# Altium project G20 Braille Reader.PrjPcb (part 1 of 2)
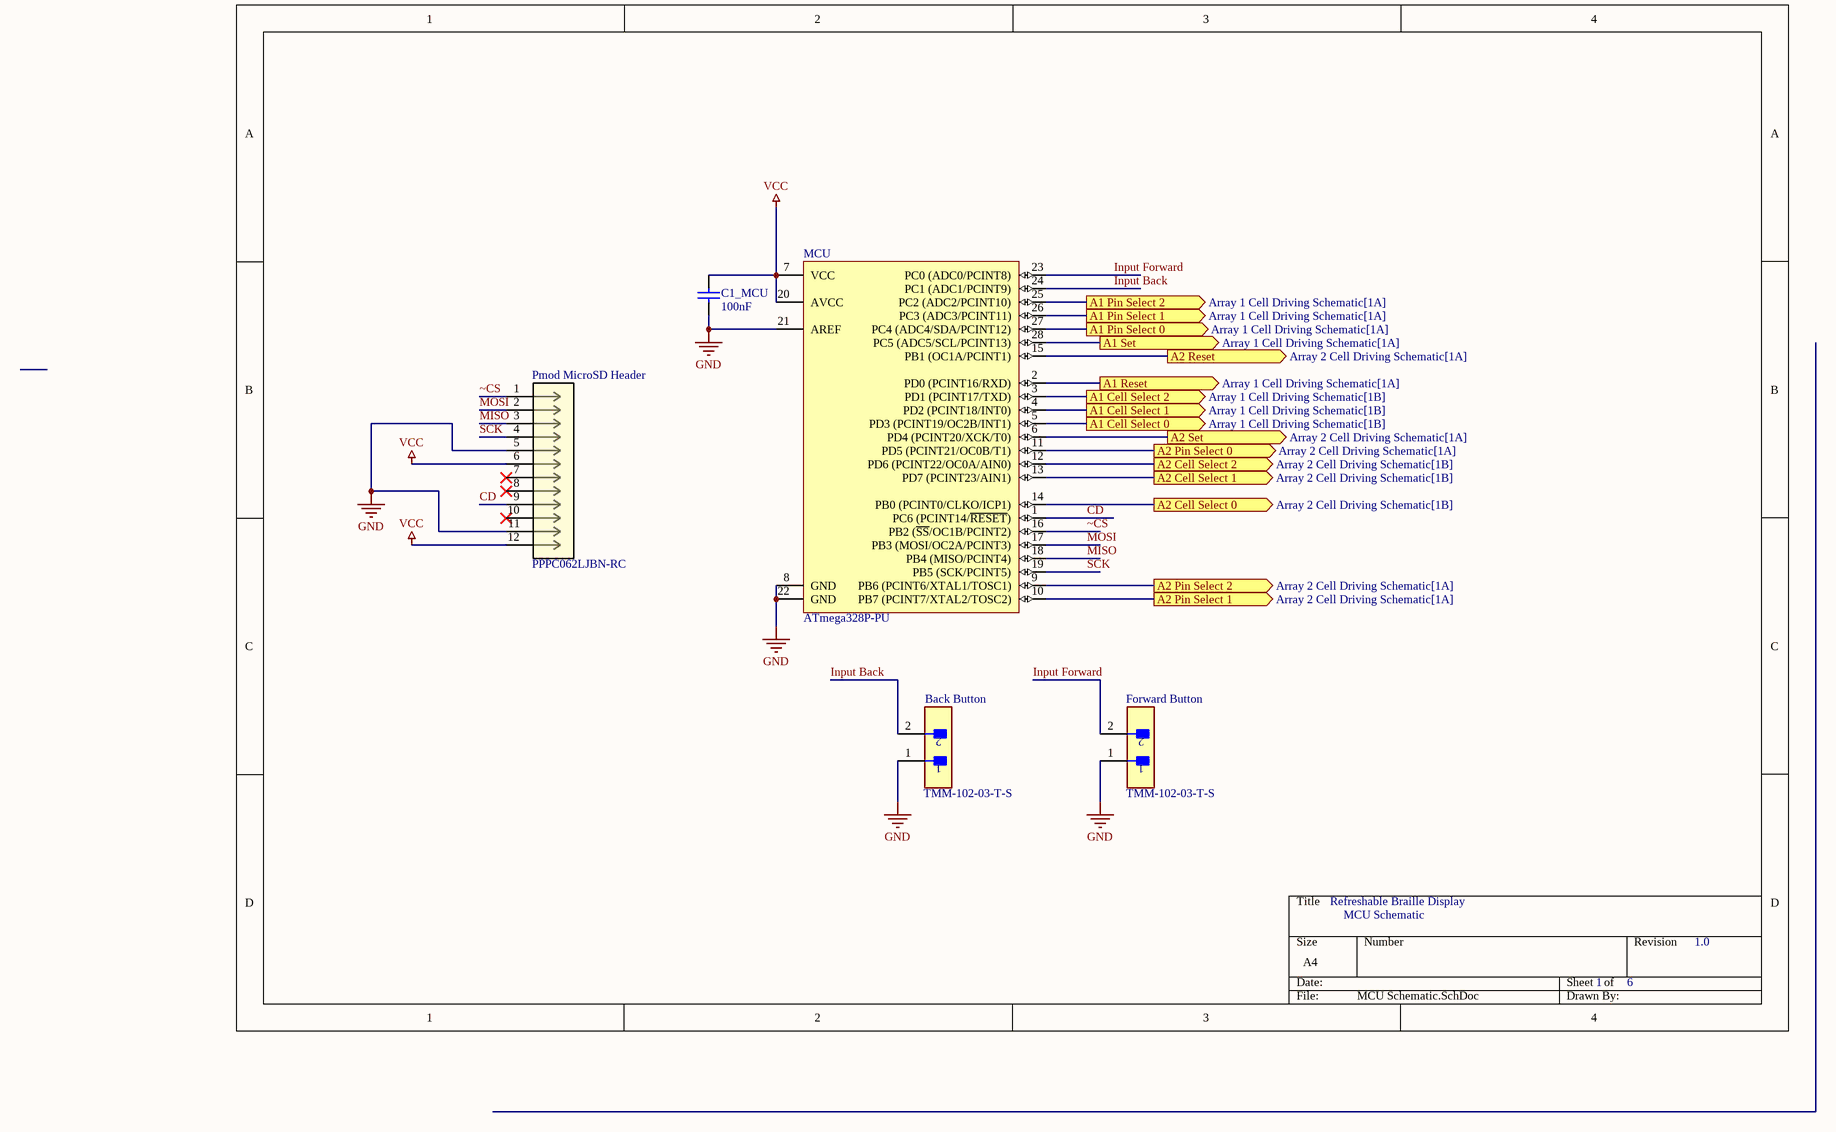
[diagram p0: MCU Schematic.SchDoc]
6 sheets, 206 parts. Net scope: flat (ports and power ports of the same name join across sheets).
Board files: G20 Braille Reader PCB.PcbDoc, Braille Cell.PcbDoc, G20 PCB Print.PcbDoc
Sheets:
  MCU Schematic.SchDoc
  Array 1 Cell Driving Schematic.SchDoc
  Array 1 Braille Cell Schematic.SchDoc
  Array 2 Cell Driving Schematic.SchDoc
  Array 2 Braille Cell Schematic.SchDoc
  Power and Voltage Regulation Schematic.SchDoc

## Sheet MCU Schematic.SchDoc
size A4; SheetNumber: 1; SheetTotal: 6

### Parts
Back_Button  TMM-102-03-T-S  [FP-TMM-102-03-T-S-MFG]
C1_MCU  100nF  [CAPC0805(2012)100_M]
Forward_Button  TMM-102-03-T-S  [FP-TMM-102-03-T-S-MFG]
MCU  ATmega328P-PU  [28P3]
Pmod_MicroSD_Header  PPPC062LJBN-RC  [CONN_PPPC062LJBN-RC_SUL]

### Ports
A1 Cell Select 0 (out, see Array 1 Cell Driving Schematic[1B]), A1 Cell Select 1 (out, see Array 1 Cell Driving Schematic[1B]), A1 Cell Select 2 (out, see Array 1 Cell Driving Schematic[1B]), A1 Pin Select 0 (out, see Array 1 Cell Driving Schematic[1A]), A1 Pin Select 1 (out, see Array 1 Cell Driving Schematic[1A]), A1 Pin Select 2 (out, see Array 1 Cell Driving Schematic[1A]), A1 Reset (out, see Array 1 Cell Driving Schematic[1A]), A1 Set (out, see Array 1 Cell Driving Schematic[1A]), A2 Cell Select 0 (out, see Array 2 Cell Driving Schematic[1B]), A2 Cell Select 1 (out, see Array 2 Cell Driving Schematic[1B]), A2 Cell Select 2 (out, see Array 2 Cell Driving Schematic[1B]), A2 Pin Select 0 (out, see Array 2 Cell Driving Schematic[1A]), A2 Pin Select 1 (out, see Array 2 Cell Driving Schematic[1A]), A2 Pin Select 2 (out, see Array 2 Cell Driving Schematic[1A]), A2 Reset (out, see Array 2 Cell Driving Schematic[1A]), A2 Set (out, see Array 2 Cell Driving Schematic[1A])

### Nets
GND: Back_Button.1 C1_MCU.1 Forward_Button.1 MCU.8(GND) MCU.21(AREF) MCU.22(GND) Pmod_MicroSD_Header.5 Pmod_MicroSD_Header.11
VCC: C1_MCU.2 MCU.7(VCC) MCU.20(AVCC) Pmod_MicroSD_Header.6 Pmod_MicroSD_Header.12
A2 Cell Select 0: MCU.14(PB0_(PCINT0/CLKO/ICP1)) ; port A2 Cell Select 0
A2 Cell Select 1: MCU.13(PD7_(PCINT23/AIN1)) ; port A2 Cell Select 1
A2 Cell Select 2: MCU.12(PD6_(PCINT22/OC0A/AIN0)) ; port A2 Cell Select 2
A2 Pin Select 0: MCU.11(PD5_(PCINT21/OC0B/T1)) ; port A2 Pin Select 0
A2 Pin Select 1: MCU.10(PB7_(PCINT7/XTAL2/TOSC2)) ; port A2 Pin Select 1
A2 Pin Select 2: MCU.9(PB6_(PCINT6/XTAL1/TOSC1)) ; port A2 Pin Select 2
CD: MCU.1(PC6_(PCINT14/~{RESET})) Pmod_MicroSD_Header.9
Cell Select 0: MCU.5(PD3_(PCINT19/OC2B/INT1)) ; port A1 Cell Select 0
Cell Select 1: MCU.4(PD2_(PCINT18/INT0)) ; port A1 Cell Select 1
Cell Select 2: MCU.3(PD1_(PCINT17/TXD)) ; port A1 Cell Select 2
Input Back: Back_Button.2 MCU.24(PC1_(ADC1/PCINT9))
Input Forward: Forward_Button.2 MCU.23(PC0_(ADC0/PCINT8))
MISO: MCU.18(PB4_(MISO/PCINT4)) Pmod_MicroSD_Header.3
MOSI: MCU.17(PB3_(MOSI/OC2A/PCINT3)) Pmod_MicroSD_Header.2
Pin Select 0: MCU.27(PC4_(ADC4/SDA/PCINT12)) ; port A1 Pin Select 0
Pin Select 1: MCU.26(PC3_(ADC3/PCINT11)) ; port A1 Pin Select 1
Pin Select 2: MCU.25(PC2_(ADC2/PCINT10)) ; port A1 Pin Select 2
SCK: MCU.19(PB5_(SCK/PCINT5)) Pmod_MicroSD_Header.4
~CS: MCU.16(PB2_(~{SS}/OC1B/PCINT2)) Pmod_MicroSD_Header.1
NetA1_Cell_Reset_Decoder_4: MCU.28(PC5_(ADC5/SCL/PCINT13)) ; port A1 Set
NetA1_Cell_Reset_Decoder_6: MCU.2(PD0_(PCINT16/RXD)) ; port A1 Reset
NetA2_Cell_Reset_Decoder_4: MCU.6(PD4_(PCINT20/XCK/T0)) ; port A2 Set
NetA2_Cell_Reset_Decoder_6: MCU.15(PB1_(OC1A/PCINT1)) ; port A2 Reset

Not connected (* = marked no-connect by the designer): Pmod_MicroSD_Header 7* 8* 10*

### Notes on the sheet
- Refreshable Braille Display
- MCU Schematic
- 1
- 6
- 1.0

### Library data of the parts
Back_Button Forward_Button = CMP-02766-001621-1: CONN HEADER VERT 2POS 2MM; Max Voltage Rating (AC): 500V; Gender: Male; Number of Positions: 2; Max Current Rating: 3.9A
C1_MCU = CMP-1036-04393-1: CAP 100nF 10V ±5% 0805 (2012 Metric) Thickness 1mm SMD; Tolerance: Â±5%; Case-EIA: 0805; Case-Metric: 2012
MCU = CMP-0095-00013-2: 8-bit AVR Microcontroller, 32KB Flash, 1KB EEPROM, 2KB SRAM, 28-pin PDIP, Industrial Grade (-40°C to 85°C)
Pmod_MicroSD_Header = PPPC062LJBN-RC: Description; Manufacturer_Name: Sullins

## Sheet Array 1 Cell Driving Schematic.SchDoc
size A4; SheetNumber: 2; SheetTotal: 6
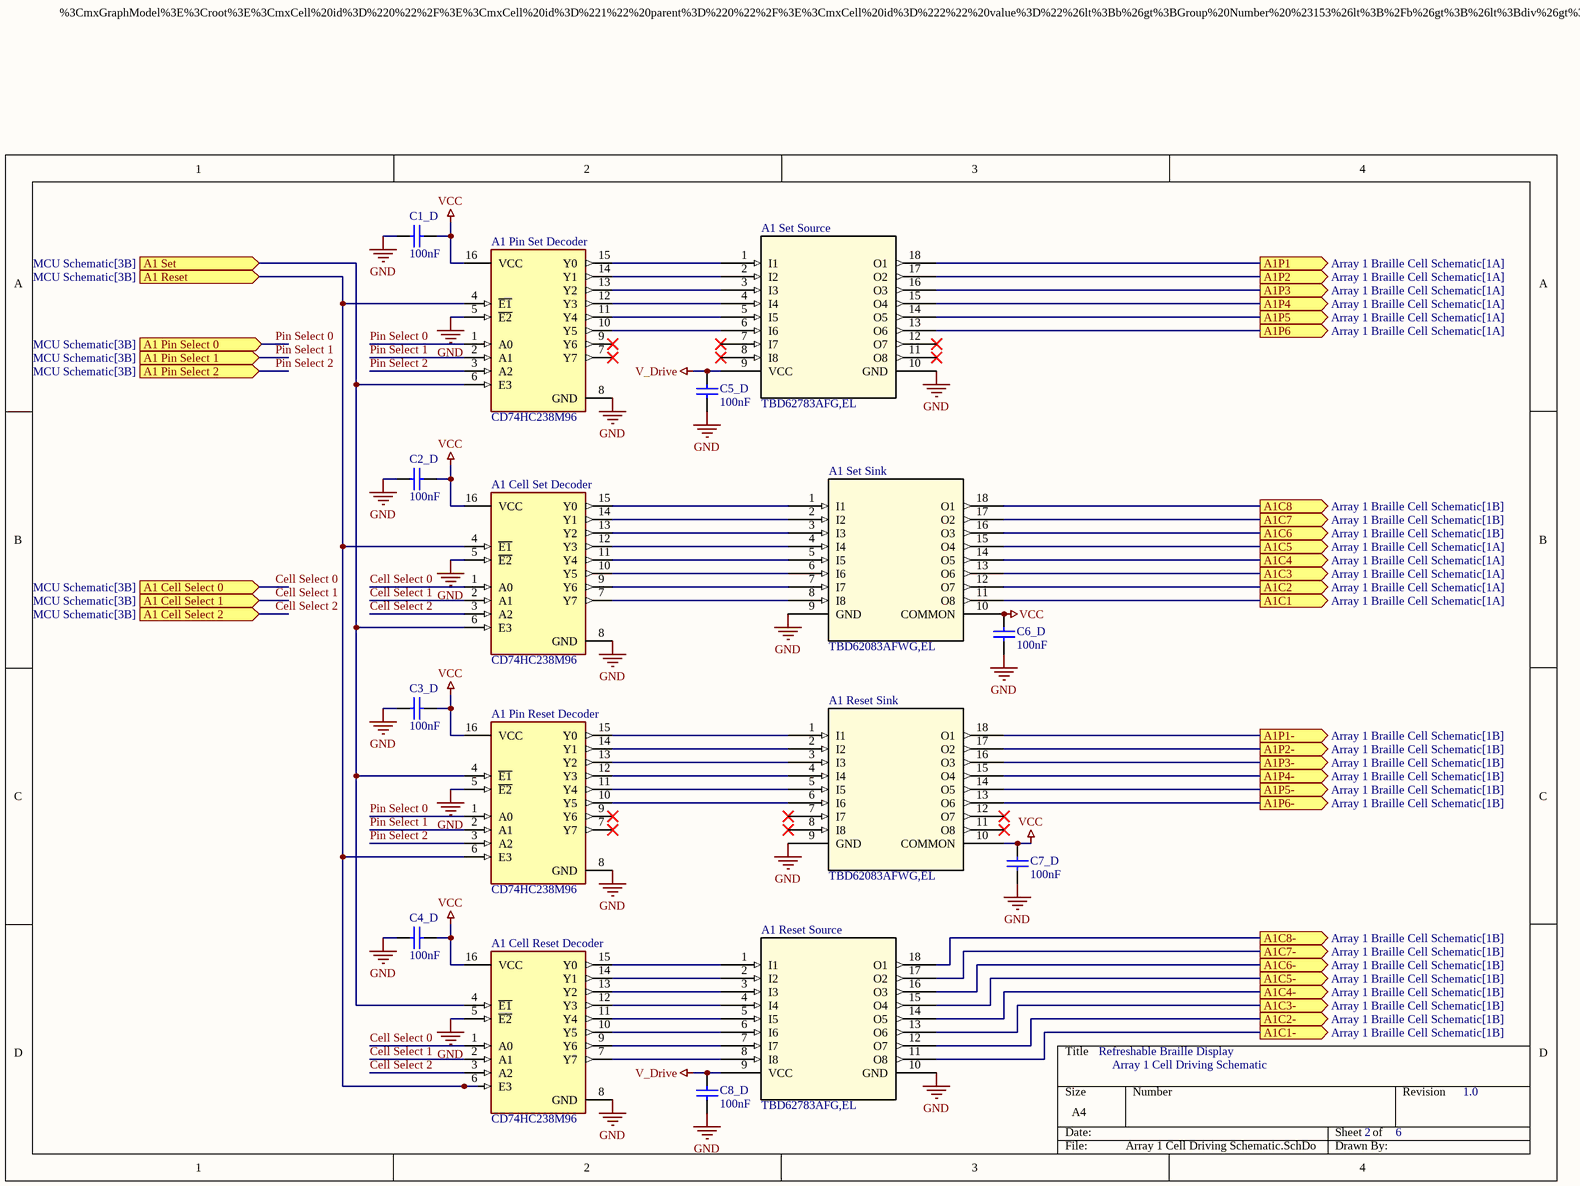
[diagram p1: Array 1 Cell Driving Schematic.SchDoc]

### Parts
A1_Cell_Reset_Decoder  CD74HC238M96  [FP-D0016A-MFG]
A1_Cell_Set_Decoder  CD74HC238M96  [FP-D0016A-MFG]
A1_Pin_Reset_Decoder  CD74HC238M96  [FP-D0016A-MFG]
A1_Pin_Set_Decoder  CD74HC238M96  [FP-D0016A-MFG]
A1_Reset_Sink  TBD62083AFWG,EL  [P-SOP18-0812-1p27-001_TOS]
A1_Reset_Source  TBD62783AFG,EL  [SOP18-P-375-1p27_TOS]
A1_Set_Sink  TBD62083AFWG,EL  [P-SOP18-0812-1p27-001_TOS]
A1_Set_Source  TBD62783AFG,EL  [SOP18-P-375-1p27_TOS]
C1_D  100nF  [CAPC0805(2012)100_M]
C2_D  100nF  [CAPC0805(2012)100_M]
C3_D  100nF  [CAPC0805(2012)100_M]
C4_D  100nF  [CAPC0805(2012)100_M]
C5_D  100nF  [CAPC0805(2012)100_M]
C6_D  100nF  [CAPC0805(2012)100_M]
C7_D  100nF  [CAPC0805(2012)100_M]
C8_D  100nF  [CAPC0805(2012)100_M]

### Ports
A1 Cell Select 0 (in, see MCU Schematic[3B]), A1 Cell Select 1 (in, see MCU Schematic[3B]), A1 Cell Select 2 (in, see MCU Schematic[3B]), A1 Pin Select 0 (in, see MCU Schematic[3B]), A1 Pin Select 1 (in, see MCU Schematic[3B]), A1 Pin Select 2 (in, see MCU Schematic[3B]), A1 Reset (in, see MCU Schematic[3B]), A1 Set (in, see MCU Schematic[3B]), A1C1 (out, see Array 1 Braille Cell Schematic[1A]), A1C1- (out, see Array 1 Braille Cell Schematic[1B]), A1C2 (out, see Array 1 Braille Cell Schematic[1A]), A1C2- (out, see Array 1 Braille Cell Schematic[1B]), A1C3 (out, see Array 1 Braille Cell Schematic[1A]), A1C3- (out, see Array 1 Braille Cell Schematic[1B]), A1C4 (out, see Array 1 Braille Cell Schematic[1A]), A1C4- (out, see Array 1 Braille Cell Schematic[1B]), A1C5 (out, see Array 1 Braille Cell Schematic[1A]), A1C5- (out, see Array 1 Braille Cell Schematic[1B]), A1C6 (out, see Array 1 Braille Cell Schematic[1B]), A1C6- (out, see Array 1 Braille Cell Schematic[1B]), A1C7 (out, see Array 1 Braille Cell Schematic[1B]), A1C7- (out, see Array 1 Braille Cell Schematic[1B]), A1C8 (out, see Array 1 Braille Cell Schematic[1B]), A1C8- (out, see Array 1 Braille Cell Schematic[1B]), A1P1 (out, see Array 1 Braille Cell Schematic[1A]), A1P1- (out, see Array 1 Braille Cell Schematic[1B]), A1P2 (out, see Array 1 Braille Cell Schematic[1A]), A1P2- (out, see Array 1 Braille Cell Schematic[1B]), A1P3 (out, see Array 1 Braille Cell Schematic[1A]), A1P3- (out, see Array 1 Braille Cell Schematic[1B]), A1P4 (out, see Array 1 Braille Cell Schematic[1A]), A1P4- (out, see Array 1 Braille Cell Schematic[1B]), A1P5 (out, see Array 1 Braille Cell Schematic[1A]), A1P5- (out, see Array 1 Braille Cell Schematic[1B]), A1P6 (out, see Array 1 Braille Cell Schematic[1A]), A1P6- (out, see Array 1 Braille Cell Schematic[1B])

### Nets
GND: A1_Cell_Reset_Decoder.5(~{E2}) A1_Cell_Reset_Decoder.8(GND) A1_Cell_Set_Decoder.5(~{E2}) A1_Cell_Set_Decoder.8(GND) A1_Pin_Reset_Decoder.5(~{E2}) A1_Pin_Reset_Decoder.8(GND) A1_Pin_Set_Decoder.5(~{E2}) A1_Pin_Set_Decoder.8(GND) A1_Reset_Sink.9(GND) A1_Reset_Source.10(GND) A1_Set_Sink.9(GND) A1_Set_Source.10(GND) C1_D.2 C2_D.2 C3_D.2 C4_D.2 C5_D.1 C6_D.1 C7_D.1 C8_D.1
V_Drive: A1_Reset_Source.9(VCC) A1_Set_Source.9(VCC) C5_D.2 C8_D.2
VCC: A1_Cell_Reset_Decoder.16(VCC) A1_Cell_Set_Decoder.16(VCC) A1_Pin_Reset_Decoder.16(VCC) A1_Pin_Set_Decoder.16(VCC) A1_Reset_Sink.10(COMMON) A1_Set_Sink.10(COMMON) C1_D.1 C2_D.1 C3_D.1 C4_D.1 C6_D.2 C7_D.2
A1 Cell1: A1_Set_Sink.11(O8) ; port A1C1
A1 Cell1 Reset: A1_Reset_Source.11(O8) ; port A1C1-
A1 Cell2: A1_Set_Sink.12(O7) ; port A1C2
A1 Cell2 Reset: A1_Reset_Source.12(O7) ; port A1C2-
A1 Cell3: A1_Set_Sink.13(O6) ; port A1C3
A1 Cell3 Reset: A1_Reset_Source.13(O6) ; port A1C3-
A1 Cell4: A1_Set_Sink.14(O5) ; port A1C4
A1 Cell4 Reset: A1_Reset_Source.14(O5) ; port A1C4-
A1 Cell5: A1_Set_Sink.15(O4) ; port A1C5
A1 Cell5 Reset: A1_Reset_Source.15(O4) ; port A1C5-
A1 Cell6: A1_Set_Sink.16(O3) ; port A1C6
A1 Cell6 Reset: A1_Reset_Source.16(O3) ; port A1C6-
A1 Cell7: A1_Set_Sink.17(O2) ; port A1C7
A1 Cell7 Reset: A1_Reset_Source.17(O2) ; port A1C7-
A1 Cell8: A1_Set_Sink.18(O1) ; port A1C8
A1 Cell8 Reset: A1_Reset_Source.18(O1) ; port A1C8-
A1 Pin1: A1_Set_Source.18(O1) ; port A1P1
A1 Pin1 Reset: A1_Reset_Sink.18(O1) ; port A1P1-
A1 Pin2: A1_Set_Source.17(O2) ; port A1P2
A1 Pin2 Reset: A1_Reset_Sink.17(O2) ; port A1P2-
A1 Pin3: A1_Set_Source.16(O3) ; port A1P3
A1 Pin3 Reset: A1_Reset_Sink.16(O3) ; port A1P3-
A1 Pin4: A1_Set_Source.15(O4) ; port A1P4
A1 Pin4 Reset: A1_Reset_Sink.15(O4) ; port A1P4-
A1 Pin5: A1_Set_Source.14(O5) ; port A1P5
A1 Pin5 Reset: A1_Reset_Sink.14(O5) ; port A1P5-
A1 Pin6: A1_Set_Source.13(O6) ; port A1P6
A1 Pin6 Reset: A1_Reset_Sink.13(O6) ; port A1P6-
Cell Select 0: A1_Cell_Reset_Decoder.1(A0) A1_Cell_Set_Decoder.1(A0) ; port A1 Cell Select 0
Cell Select 1: A1_Cell_Reset_Decoder.2(A1) A1_Cell_Set_Decoder.2(A1) ; port A1 Cell Select 1
Cell Select 2: A1_Cell_Reset_Decoder.3(A2) A1_Cell_Set_Decoder.3(A2) ; port A1 Cell Select 2
Pin Select 0: A1_Pin_Reset_Decoder.1(A0) A1_Pin_Set_Decoder.1(A0) ; port A1 Pin Select 0
Pin Select 1: A1_Pin_Reset_Decoder.2(A1) A1_Pin_Set_Decoder.2(A1) ; port A1 Pin Select 1
Pin Select 2: A1_Pin_Reset_Decoder.3(A2) A1_Pin_Set_Decoder.3(A2) ; port A1 Pin Select 2
NetA1_Cell_Reset_Decoder_4: A1_Cell_Reset_Decoder.4(~{E1}) A1_Cell_Set_Decoder.6(E3) A1_Pin_Reset_Decoder.4(~{E1}) A1_Pin_Set_Decoder.6(E3) ; port A1 Set
NetA1_Cell_Reset_Decoder_6: A1_Cell_Reset_Decoder.6(E3) A1_Cell_Set_Decoder.4(~{E1}) A1_Pin_Reset_Decoder.6(E3) A1_Pin_Set_Decoder.4(~{E1}) ; port A1 Reset
NetA1_Cell_Reset_Decoder_7: A1_Cell_Reset_Decoder.7(Y7) A1_Reset_Source.8(I8)
NetA1_Cell_Reset_Decoder_9: A1_Cell_Reset_Decoder.9(Y6) A1_Reset_Source.7(I7)
NetA1_Cell_Reset_Decoder_10: A1_Cell_Reset_Decoder.10(Y5) A1_Reset_Source.6(I6)
NetA1_Cell_Reset_Decoder_11: A1_Cell_Reset_Decoder.11(Y4) A1_Reset_Source.5(I5)
NetA1_Cell_Reset_Decoder_12: A1_Cell_Reset_Decoder.12(Y3) A1_Reset_Source.4(I4)
NetA1_Cell_Reset_Decoder_13: A1_Cell_Reset_Decoder.13(Y2) A1_Reset_Source.3(I3)
NetA1_Cell_Reset_Decoder_14: A1_Cell_Reset_Decoder.14(Y1) A1_Reset_Source.2(I2)
NetA1_Cell_Reset_Decoder_15: A1_Cell_Reset_Decoder.15(Y0) A1_Reset_Source.1(I1)
NetA1_Cell_Set_Decoder_7: A1_Cell_Set_Decoder.7(Y7) A1_Set_Sink.8(I8)
NetA1_Cell_Set_Decoder_9: A1_Cell_Set_Decoder.9(Y6) A1_Set_Sink.7(I7)
NetA1_Cell_Set_Decoder_10: A1_Cell_Set_Decoder.10(Y5) A1_Set_Sink.6(I6)
NetA1_Cell_Set_Decoder_11: A1_Cell_Set_Decoder.11(Y4) A1_Set_Sink.5(I5)
NetA1_Cell_Set_Decoder_12: A1_Cell_Set_Decoder.12(Y3) A1_Set_Sink.4(I4)
NetA1_Cell_Set_Decoder_13: A1_Cell_Set_Decoder.13(Y2) A1_Set_Sink.3(I3)
NetA1_Cell_Set_Decoder_14: A1_Cell_Set_Decoder.14(Y1) A1_Set_Sink.2(I2)
NetA1_Cell_Set_Decoder_15: A1_Cell_Set_Decoder.15(Y0) A1_Set_Sink.1(I1)
NetA1_Pin_Reset_Decoder_10: A1_Pin_Reset_Decoder.10(Y5) A1_Reset_Sink.6(I6)
NetA1_Pin_Reset_Decoder_11: A1_Pin_Reset_Decoder.11(Y4) A1_Reset_Sink.5(I5)
NetA1_Pin_Reset_Decoder_12: A1_Pin_Reset_Decoder.12(Y3) A1_Reset_Sink.4(I4)
NetA1_Pin_Reset_Decoder_13: A1_Pin_Reset_Decoder.13(Y2) A1_Reset_Sink.3(I3)
NetA1_Pin_Reset_Decoder_14: A1_Pin_Reset_Decoder.14(Y1) A1_Reset_Sink.2(I2)
NetA1_Pin_Reset_Decoder_15: A1_Pin_Reset_Decoder.15(Y0) A1_Reset_Sink.1(I1)
NetA1_Pin_Set_Decoder_10: A1_Pin_Set_Decoder.10(Y5) A1_Set_Source.6(I6)
NetA1_Pin_Set_Decoder_11: A1_Pin_Set_Decoder.11(Y4) A1_Set_Source.5(I5)
NetA1_Pin_Set_Decoder_12: A1_Pin_Set_Decoder.12(Y3) A1_Set_Source.4(I4)
NetA1_Pin_Set_Decoder_13: A1_Pin_Set_Decoder.13(Y2) A1_Set_Source.3(I3)
NetA1_Pin_Set_Decoder_14: A1_Pin_Set_Decoder.14(Y1) A1_Set_Source.2(I2)
NetA1_Pin_Set_Decoder_15: A1_Pin_Set_Decoder.15(Y0) A1_Set_Source.1(I1)

Not connected (* = marked no-connect by the designer): A1_Pin_Reset_Decoder 7(Y7)* 9(Y6)*; A1_Pin_Set_Decoder 7(Y7)* 9(Y6)*; A1_Reset_Sink 7(I7)* 8(I8)* 11(O8)* 12(O7)*; A1_Set_Source 7(I7)* 8(I8)* 11(O8)* 12(O7)*

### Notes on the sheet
- %3CmxGraphModel%3E%3Croot%3E%3CmxCell%20id%3D%220%22%2F%3E%3CmxCell%20id%3D%221%22%20parent%3D%220%22%2F%3E%3CmxCell%20id%3D%222%22%20value%3D%22%26lt%3Bb%26gt%3BGroup%20Number%20%23153%26lt%3B%2Fb%26gt%3B%26lt%3Bdiv%26gt%3B%26lt%3Bb%26gt%3B%26lt%3Bbr%26gt%3B%26lt%3B%2Fb%26gt%3B%26lt%3Bdiv%26gt%3B%26lt%3Bspan%20style%3D%26quot%3Bbackground-color%3A%20transparent%3B%20color%3A%20light-dark(rgb(0%2C%200%2C%200)%2C%20rgb(255%2C%20255%2C%20255))%3B%26quot%3B%26gt%3BAlbert%20Li%201661902%26lt%3B%2Fspan%26gt%3B%26lt%3B%2Fdiv%26gt%3B%26lt%3Bdiv%26gt%3BWiktoria%20Klimczak%201778458%26lt%3B%2Fdiv%26gt%3B%26lt%3Bdiv%26gt%3BVivien%20Cen%201702106%26lt%3B%2Fdiv%26gt%3B%26lt%3Bdiv%26gt%3BCatherine%20Milliken%201614973%26lt%3B%2Fdiv%26gt%3B%26lt%3Bdiv%26gt%3BKatharine%20Zhong%201707425%26lt%3B%2Fdiv%26gt%3B%26lt%3B%2Fdiv%26gt%3B%22%20style%3D%22rounded%3D0%3BwhiteSpace%3Dwrap%3Bhtml%3D1%3Balign%3Dleft%3B%22%20vertex%3D%221%22%20parent%3D%221%22%3E%3CmxGeometry%20x%3D%22-1770%22%20y%3D%2228.5%22%20width%3D%22310%22%20height%3D%22110%22%20as%3D%22geometry%22%2F%3E%3C%2FmxCell%3E%3C%2Froot%3E%3C%2FmxGraphModel%3E
- Refreshable Braille Display
- Array 1 Cell Driving Schematic
- 2
- 6
- 1.0

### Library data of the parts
A1_Cell_Reset_Decoder A1_Cell_Set_Decoder A1_Pin_Reset_Decoder A1_Pin_Set_Decoder = CMP-1633-00102-3: IC 3-8 DECODER/DEMUX HS 16-SOIC; Manufacturer: Texas Instruments; Number Of Inputs: 6; Max Junction Temp: +150°C; Max Supply Voltage: 6V; Number Of Circuits: 1; Min Supply Voltage: 2V; Standoff Height: 0.25mm; Number Of Outputs: 8; Propagation Delay: 13ns; Quiescent Current: 8uA
A1_Reset_Sink A1_Set_Sink = TBD62083AFWG,EL: Description; Manufacturer_Name: Toshiba Electronic Devices & Storage Corp.
A1_Reset_Source A1_Set_Source = TBD62783AFG,EL: Description; Manufacturer_Name: Toshiba Electronic Devices & Storage Corp.
C1_D C2_D C3_D C4_D C5_D C6_D C7_D C8_D = CMP-1036-04393-1: as C1_MCU on sheet MCU Schematic

## Sheet Array 1 Braille Cell Schematic.SchDoc
size D; SheetNumber: 3; SheetTotal: 6
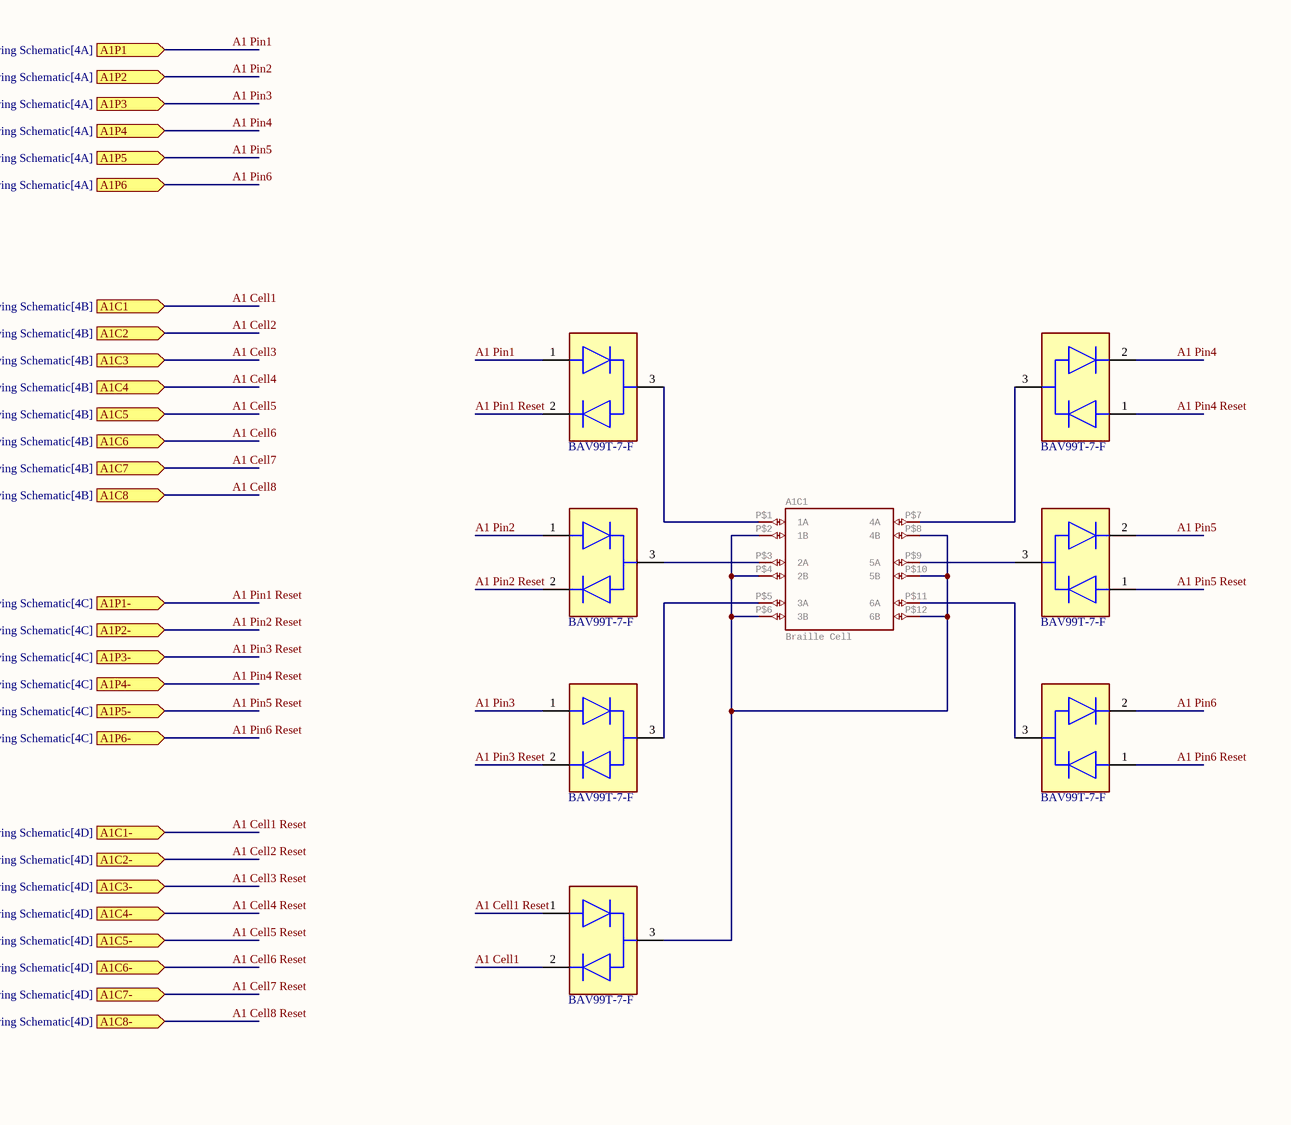
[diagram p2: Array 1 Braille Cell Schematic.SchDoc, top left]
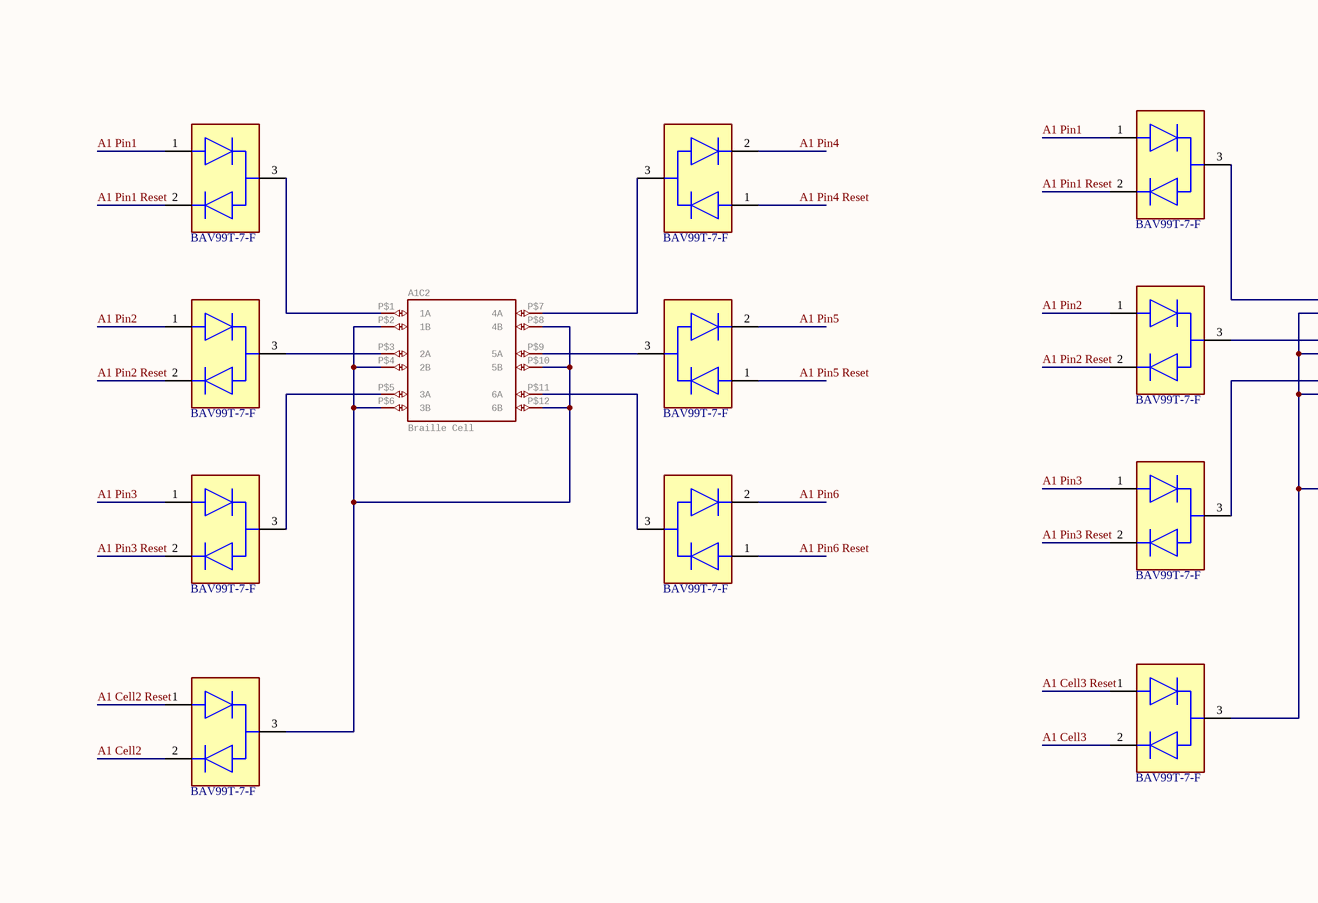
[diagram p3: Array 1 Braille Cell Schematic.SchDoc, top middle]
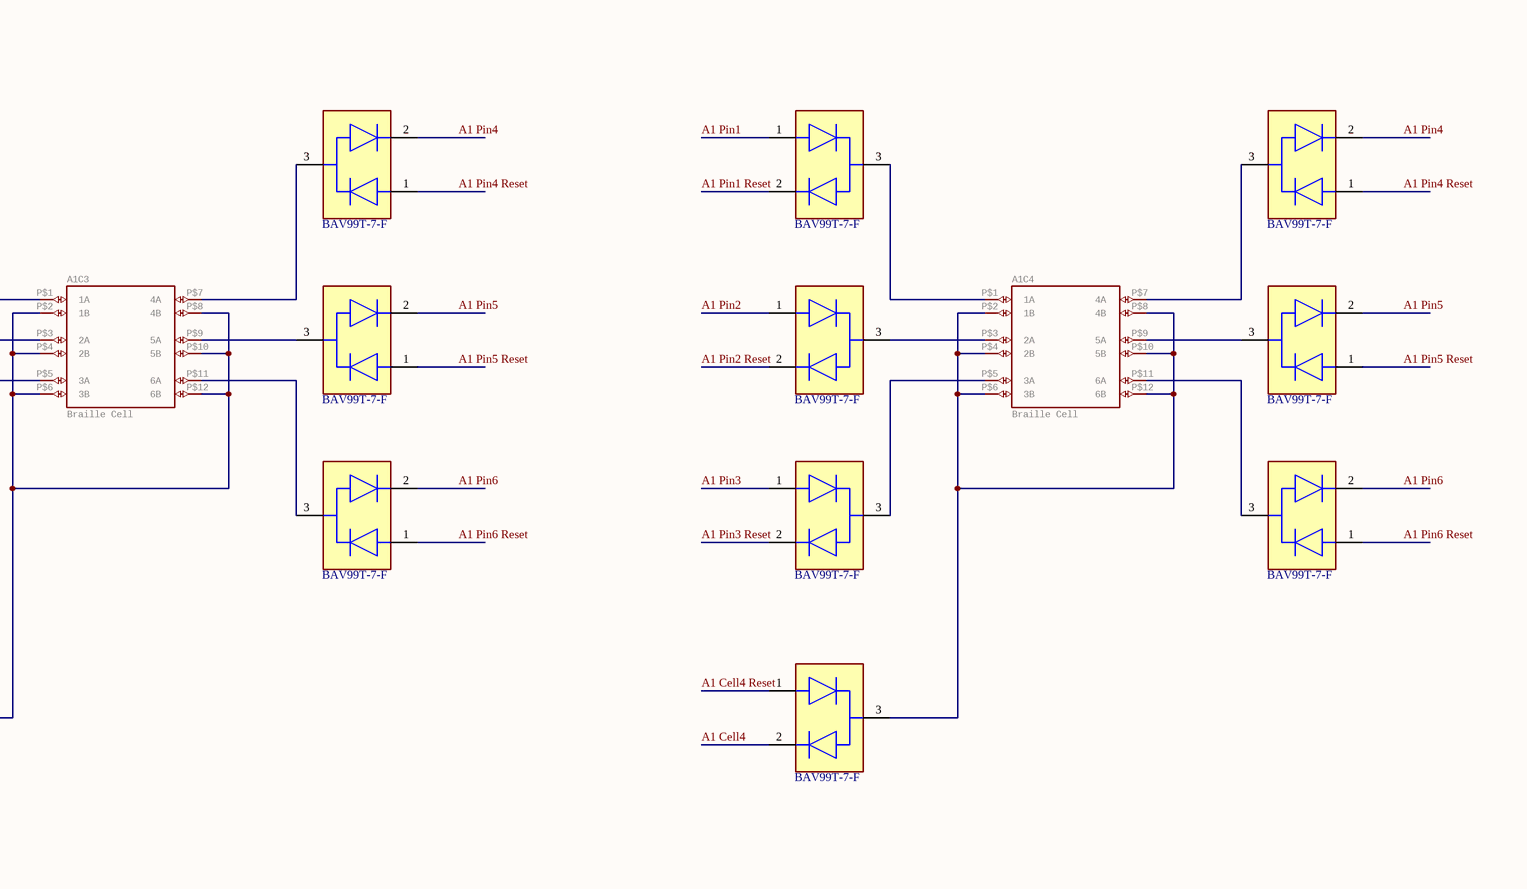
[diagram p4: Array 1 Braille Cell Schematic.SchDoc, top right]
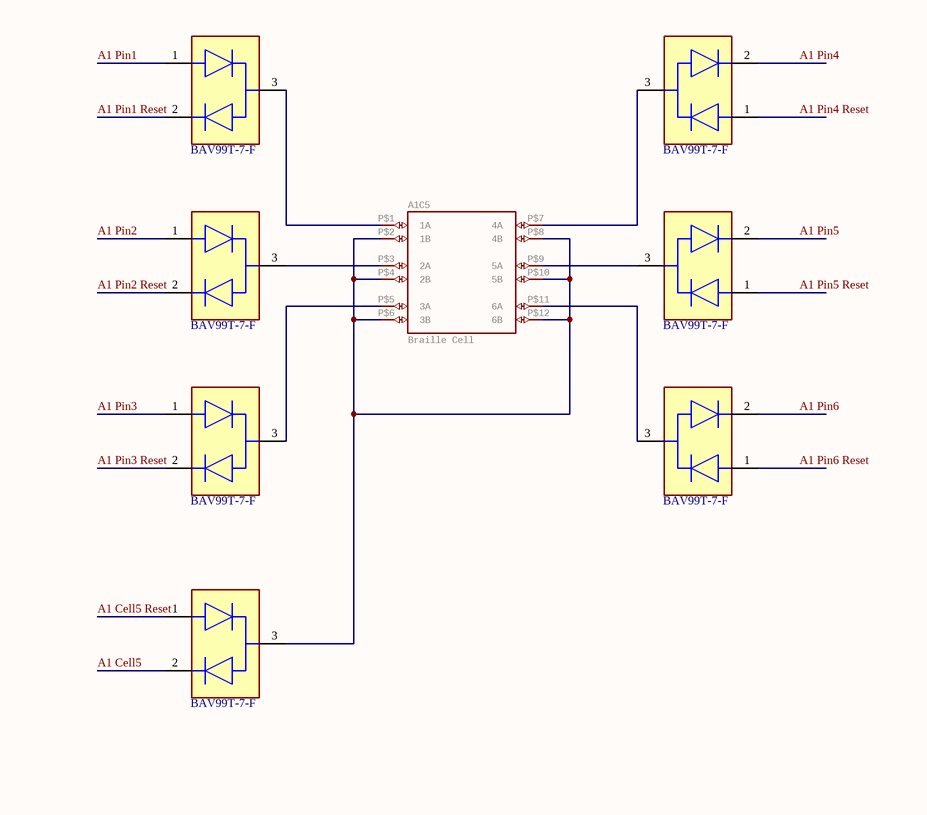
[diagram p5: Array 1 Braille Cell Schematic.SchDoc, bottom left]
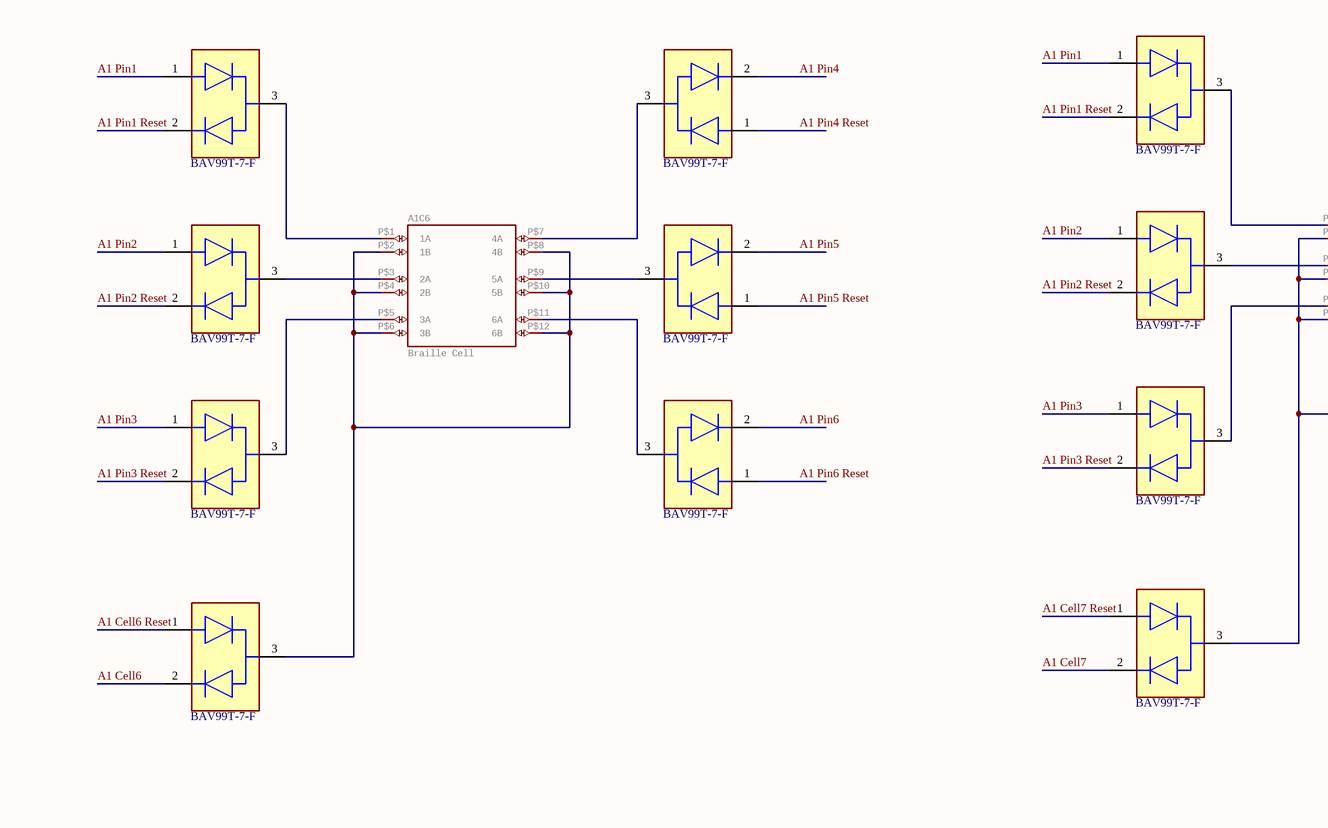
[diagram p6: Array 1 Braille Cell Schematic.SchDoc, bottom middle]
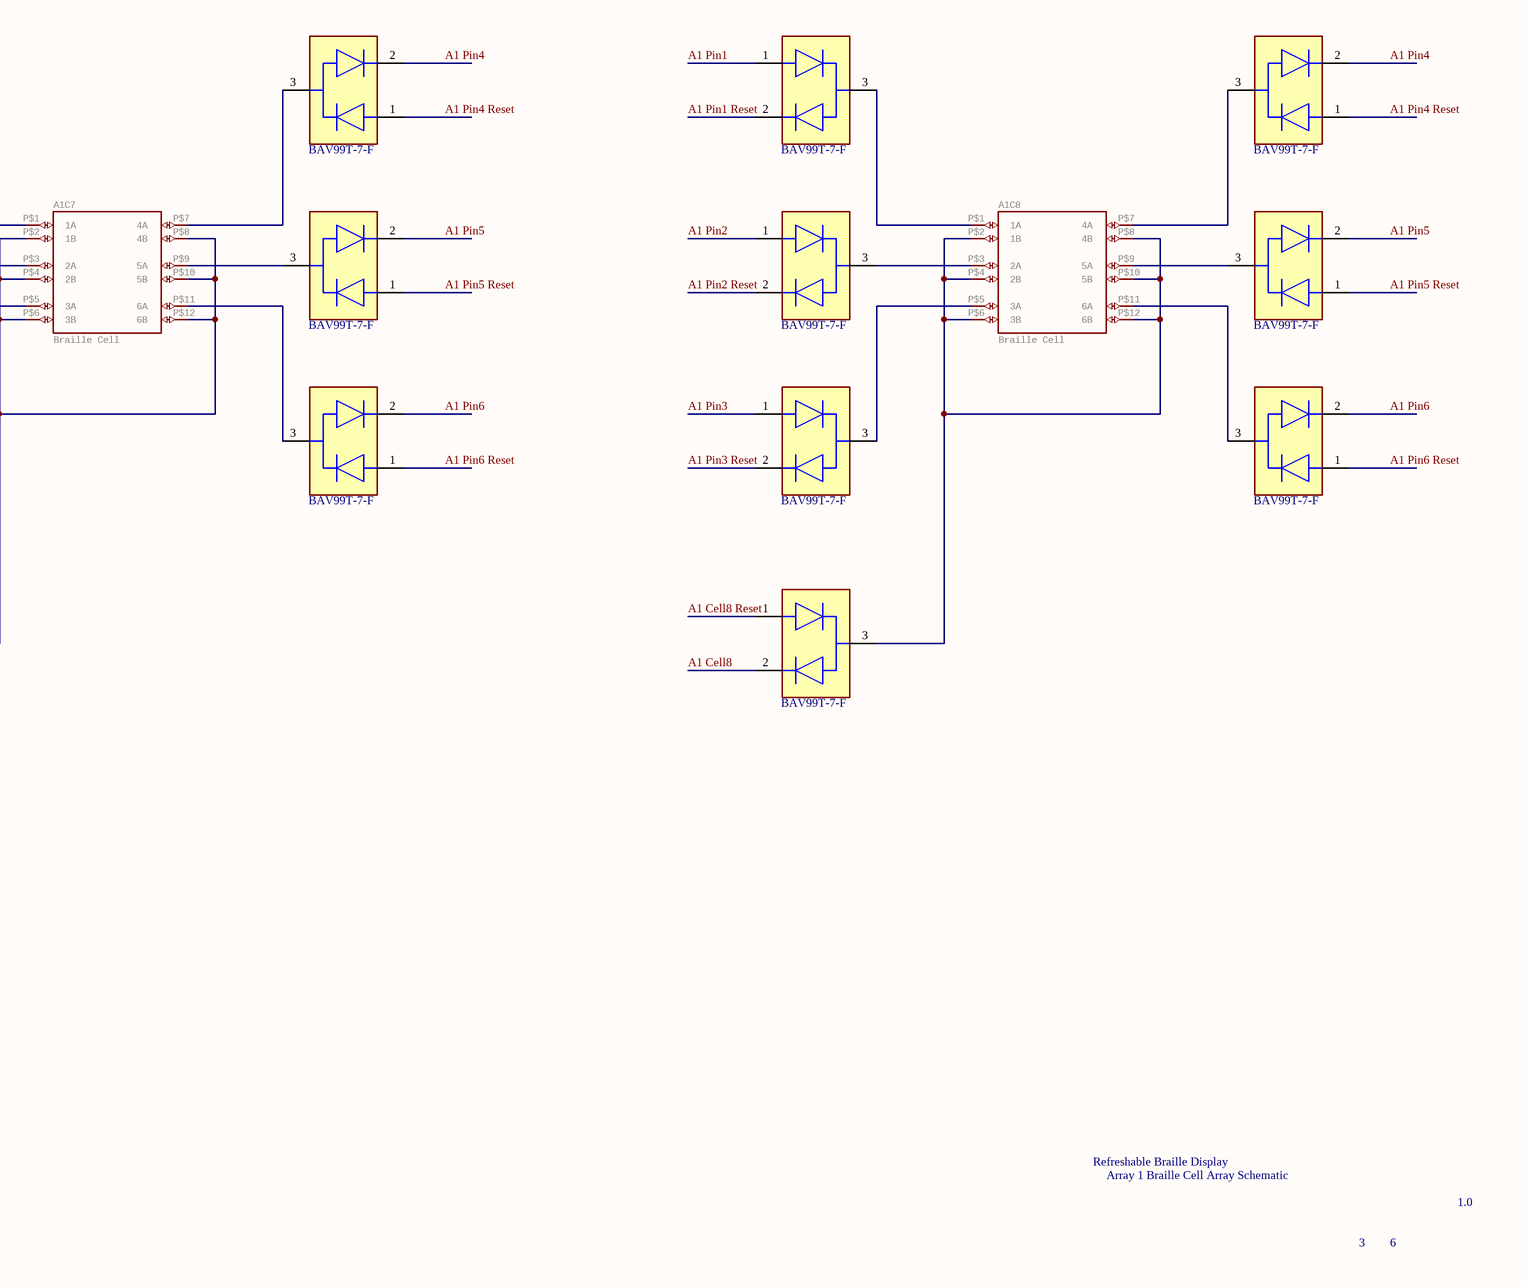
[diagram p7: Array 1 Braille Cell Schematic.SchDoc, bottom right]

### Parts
A1C1  Braille Cell  [BRAILLE-6]
A1C2  Braille Cell  [BRAILLE-6]
A1C3  Braille Cell  [BRAILLE-6]
A1C4  Braille Cell  [BRAILLE-6]
A1C5  Braille Cell  [BRAILLE-6]
A1C6  Braille Cell  [BRAILLE-6]
A1C7  Braille Cell  [BRAILLE-6]
A1C8  Braille Cell  [BRAILLE-6]
A1D1C1  BAV99T-7-F  [FP-SOT523-MFG]
A1D1C2  BAV99T-7-F  [FP-SOT523-MFG]
A1D1C3  BAV99T-7-F  [FP-SOT523-MFG]
A1D1C4  BAV99T-7-F  [FP-SOT523-MFG]
A1D1C5  BAV99T-7-F  [FP-SOT523-MFG]
A1D1C6  BAV99T-7-F  [FP-SOT523-MFG]
A1D1C7  BAV99T-7-F  [FP-SOT523-MFG]
A1D1C8  BAV99T-7-F  [FP-SOT523-MFG]
A1D2C1  BAV99T-7-F  [FP-SOT523-MFG]
A1D2C2  BAV99T-7-F  [FP-SOT523-MFG]
A1D2C3  BAV99T-7-F  [FP-SOT523-MFG]
A1D2C4  BAV99T-7-F  [FP-SOT523-MFG]
A1D2C5  BAV99T-7-F  [FP-SOT523-MFG]
A1D2C6  BAV99T-7-F  [FP-SOT523-MFG]
A1D2C7  BAV99T-7-F  [FP-SOT523-MFG]
A1D2C8  BAV99T-7-F  [FP-SOT523-MFG]
A1D3C1  BAV99T-7-F  [FP-SOT523-MFG]
A1D3C2  BAV99T-7-F  [FP-SOT523-MFG]
A1D3C3  BAV99T-7-F  [FP-SOT523-MFG]
A1D3C4  BAV99T-7-F  [FP-SOT523-MFG]
A1D3C5  BAV99T-7-F  [FP-SOT523-MFG]
A1D3C6  BAV99T-7-F  [FP-SOT523-MFG]
A1D3C7  BAV99T-7-F  [FP-SOT523-MFG]
A1D3C8  BAV99T-7-F  [FP-SOT523-MFG]
A1D4C1  BAV99T-7-F  [FP-SOT523-MFG]
A1D4C2  BAV99T-7-F  [FP-SOT523-MFG]
A1D4C3  BAV99T-7-F  [FP-SOT523-MFG]
A1D4C4  BAV99T-7-F  [FP-SOT523-MFG]
A1D4C5  BAV99T-7-F  [FP-SOT523-MFG]
A1D4C6  BAV99T-7-F  [FP-SOT523-MFG]
A1D4C7  BAV99T-7-F  [FP-SOT523-MFG]
A1D4C8  BAV99T-7-F  [FP-SOT523-MFG]
A1D5C1  BAV99T-7-F  [FP-SOT523-MFG]
A1D5C2  BAV99T-7-F  [FP-SOT523-MFG]
A1D5C3  BAV99T-7-F  [FP-SOT523-MFG]
A1D5C4  BAV99T-7-F  [FP-SOT523-MFG]
A1D5C5  BAV99T-7-F  [FP-SOT523-MFG]
A1D5C6  BAV99T-7-F  [FP-SOT523-MFG]
A1D5C7  BAV99T-7-F  [FP-SOT523-MFG]
A1D5C8  BAV99T-7-F  [FP-SOT523-MFG]
A1D6C1  BAV99T-7-F  [FP-SOT523-MFG]
A1D6C2  BAV99T-7-F  [FP-SOT523-MFG]
A1D6C3  BAV99T-7-F  [FP-SOT523-MFG]
A1D6C4  BAV99T-7-F  [FP-SOT523-MFG]
A1D6C5  BAV99T-7-F  [FP-SOT523-MFG]
A1D6C6  BAV99T-7-F  [FP-SOT523-MFG]
A1D6C7  BAV99T-7-F  [FP-SOT523-MFG]
A1D6C8  BAV99T-7-F  [FP-SOT523-MFG]
A1D7C1  BAV99T-7-F  [FP-SOT523-MFG]
A1D7C2  BAV99T-7-F  [FP-SOT523-MFG]
A1D7C3  BAV99T-7-F  [FP-SOT523-MFG]
A1D7C4  BAV99T-7-F  [FP-SOT523-MFG]
A1D7C5  BAV99T-7-F  [FP-SOT523-MFG]
A1D7C6  BAV99T-7-F  [FP-SOT523-MFG]
A1D7C7  BAV99T-7-F  [FP-SOT523-MFG]
A1D7C8  BAV99T-7-F  [FP-SOT523-MFG]

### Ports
A1C1 (in, see Array 1 Cell Driving Schematic[4B]), A1C1- (in, see Array 1 Cell Driving Schematic[4D]), A1C2 (in, see Array 1 Cell Driving Schematic[4B]), A1C2- (in, see Array 1 Cell Driving Schematic[4D]), A1C3 (in, see Array 1 Cell Driving Schematic[4B]), A1C3- (in, see Array 1 Cell Driving Schematic[4D]), A1C4 (in, see Array 1 Cell Driving Schematic[4B]), A1C4- (in, see Array 1 Cell Driving Schematic[4D]), A1C5 (in, see Array 1 Cell Driving Schematic[4B]), A1C5- (in, see Array 1 Cell Driving Schematic[4D]), A1C6 (in, see Array 1 Cell Driving Schematic[4B]), A1C6- (in, see Array 1 Cell Driving Schematic[4D]), A1C7 (in, see Array 1 Cell Driving Schematic[4B]), A1C7- (in, see Array 1 Cell Driving Schematic[4D]), A1C8 (in, see Array 1 Cell Driving Schematic[4B]), A1C8- (in, see Array 1 Cell Driving Schematic[4D]), A1P1 (in, see Array 1 Cell Driving Schematic[4A]), A1P1- (in, see Array 1 Cell Driving Schematic[4C]), A1P2 (in, see Array 1 Cell Driving Schematic[4A]), A1P2- (in, see Array 1 Cell Driving Schematic[4C]), A1P3 (in, see Array 1 Cell Driving Schematic[4A]), A1P3- (in, see Array 1 Cell Driving Schematic[4C]), A1P4 (in, see Array 1 Cell Driving Schematic[4A]), A1P4- (in, see Array 1 Cell Driving Schematic[4C]), A1P5 (in, see Array 1 Cell Driving Schematic[4A]), A1P5- (in, see Array 1 Cell Driving Schematic[4C]), A1P6 (in, see Array 1 Cell Driving Schematic[4A]), A1P6- (in, see Array 1 Cell Driving Schematic[4C])

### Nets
A1 Cell1: A1D7C1.2 ; port A1C1
A1 Cell1 Reset: A1D7C1.1 ; port A1C1-
A1 Cell2: A1D7C2.2 ; port A1C2
A1 Cell2 Reset: A1D7C2.1 ; port A1C2-
A1 Cell3: A1D7C3.2 ; port A1C3
A1 Cell3 Reset: A1D7C3.1 ; port A1C3-
A1 Cell4: A1D7C4.2 ; port A1C4
A1 Cell4 Reset: A1D7C4.1 ; port A1C4-
A1 Cell5: A1D7C5.2 ; port A1C5
A1 Cell5 Reset: A1D7C5.1 ; port A1C5-
A1 Cell6: A1D7C6.2 ; port A1C6
A1 Cell6 Reset: A1D7C6.1 ; port A1C6-
A1 Cell7: A1D7C7.2 ; port A1C7
A1 Cell7 Reset: A1D7C7.1 ; port A1C7-
A1 Cell8: A1D7C8.2 ; port A1C8
A1 Cell8 Reset: A1D7C8.1 ; port A1C8-
A1 Pin1: A1D1C1.1 A1D1C2.1 A1D1C3.1 A1D1C4.1 A1D1C5.1 A1D1C6.1 A1D1C7.1 A1D1C8.1 ; port A1P1
A1 Pin1 Reset: A1D1C1.2 A1D1C2.2 A1D1C3.2 A1D1C4.2 A1D1C5.2 A1D1C6.2 A1D1C7.2 A1D1C8.2 ; port A1P1-
A1 Pin2: A1D2C1.1 A1D2C2.1 A1D2C3.1 A1D2C4.1 A1D2C5.1 A1D2C6.1 A1D2C7.1 A1D2C8.1 ; port A1P2
A1 Pin2 Reset: A1D2C1.2 A1D2C2.2 A1D2C3.2 A1D2C4.2 A1D2C5.2 A1D2C6.2 A1D2C7.2 A1D2C8.2 ; port A1P2-
A1 Pin3: A1D3C1.1 A1D3C2.1 A1D3C3.1 A1D3C4.1 A1D3C5.1 A1D3C6.1 A1D3C7.1 A1D3C8.1 ; port A1P3
A1 Pin3 Reset: A1D3C1.2 A1D3C2.2 A1D3C3.2 A1D3C4.2 A1D3C5.2 A1D3C6.2 A1D3C7.2 A1D3C8.2 ; port A1P3-
A1 Pin4: A1D4C1.2 A1D4C2.2 A1D4C3.2 A1D4C4.2 A1D4C5.2 A1D4C6.2 A1D4C7.2 A1D4C8.2 ; port A1P4
A1 Pin4 Reset: A1D4C1.1 A1D4C2.1 A1D4C3.1 A1D4C4.1 A1D4C5.1 A1D4C6.1 A1D4C7.1 A1D4C8.1 ; port A1P4-
A1 Pin5: A1D5C1.2 A1D5C2.2 A1D5C3.2 A1D5C4.2 A1D5C5.2 A1D5C6.2 A1D5C7.2 A1D5C8.2 ; port A1P5
A1 Pin5 Reset: A1D5C1.1 A1D5C2.1 A1D5C3.1 A1D5C4.1 A1D5C5.1 A1D5C6.1 A1D5C7.1 A1D5C8.1 ; port A1P5-
A1 Pin6: A1D6C1.2 A1D6C2.2 A1D6C3.2 A1D6C4.2 A1D6C5.2 A1D6C6.2 A1D6C7.2 A1D6C8.2 ; port A1P6
A1 Pin6 Reset: A1D6C1.1 A1D6C2.1 A1D6C3.1 A1D6C4.1 A1D6C5.1 A1D6C6.1 A1D6C7.1 A1D6C8.1 ; port A1P6-
NetA1C1_P$1: A1C1.P$1(1A) A1D1C1.3
NetA1C1_P$2: A1C1.P$2(1B) A1C1.P$4(2B) A1C1.P$6(3B) A1C1.P$8(4B) A1C1.P$10(5B) A1C1.P$12(6B) A1D7C1.3
NetA1C1_P$3: A1C1.P$3(2A) A1D2C1.3
NetA1C1_P$5: A1C1.P$5(3A) A1D3C1.3
NetA1C1_P$7: A1C1.P$7(4A) A1D4C1.3
NetA1C1_P$9: A1C1.P$9(5A) A1D5C1.3
NetA1C1_P$11: A1C1.P$11(6A) A1D6C1.3
NetA1C2_P$1: A1C2.P$1(1A) A1D1C2.3
NetA1C2_P$2: A1C2.P$2(1B) A1C2.P$4(2B) A1C2.P$6(3B) A1C2.P$8(4B) A1C2.P$10(5B) A1C2.P$12(6B) A1D7C2.3
NetA1C2_P$3: A1C2.P$3(2A) A1D2C2.3
NetA1C2_P$5: A1C2.P$5(3A) A1D3C2.3
NetA1C2_P$7: A1C2.P$7(4A) A1D4C2.3
NetA1C2_P$9: A1C2.P$9(5A) A1D5C2.3
NetA1C2_P$11: A1C2.P$11(6A) A1D6C2.3
NetA1C3_P$1: A1C3.P$1(1A) A1D1C3.3
NetA1C3_P$2: A1C3.P$2(1B) A1C3.P$4(2B) A1C3.P$6(3B) A1C3.P$8(4B) A1C3.P$10(5B) A1C3.P$12(6B) A1D7C3.3
NetA1C3_P$3: A1C3.P$3(2A) A1D2C3.3
NetA1C3_P$5: A1C3.P$5(3A) A1D3C3.3
NetA1C3_P$7: A1C3.P$7(4A) A1D4C3.3
NetA1C3_P$9: A1C3.P$9(5A) A1D5C3.3
NetA1C3_P$11: A1C3.P$11(6A) A1D6C3.3
NetA1C4_P$1: A1C4.P$1(1A) A1D1C4.3
NetA1C4_P$2: A1C4.P$2(1B) A1C4.P$4(2B) A1C4.P$6(3B) A1C4.P$8(4B) A1C4.P$10(5B) A1C4.P$12(6B) A1D7C4.3
NetA1C4_P$3: A1C4.P$3(2A) A1D2C4.3
NetA1C4_P$5: A1C4.P$5(3A) A1D3C4.3
NetA1C4_P$7: A1C4.P$7(4A) A1D4C4.3
NetA1C4_P$9: A1C4.P$9(5A) A1D5C4.3
NetA1C4_P$11: A1C4.P$11(6A) A1D6C4.3
NetA1C5_P$1: A1C5.P$1(1A) A1D1C5.3
NetA1C5_P$2: A1C5.P$2(1B) A1C5.P$4(2B) A1C5.P$6(3B) A1C5.P$8(4B) A1C5.P$10(5B) A1C5.P$12(6B) A1D7C5.3
NetA1C5_P$3: A1C5.P$3(2A) A1D2C5.3
NetA1C5_P$5: A1C5.P$5(3A) A1D3C5.3
NetA1C5_P$7: A1C5.P$7(4A) A1D4C5.3
NetA1C5_P$9: A1C5.P$9(5A) A1D5C5.3
NetA1C5_P$11: A1C5.P$11(6A) A1D6C5.3
NetA1C6_P$1: A1C6.P$1(1A) A1D1C6.3
NetA1C6_P$2: A1C6.P$2(1B) A1C6.P$4(2B) A1C6.P$6(3B) A1C6.P$8(4B) A1C6.P$10(5B) A1C6.P$12(6B) A1D7C6.3
NetA1C6_P$3: A1C6.P$3(2A) A1D2C6.3
NetA1C6_P$5: A1C6.P$5(3A) A1D3C6.3
NetA1C6_P$7: A1C6.P$7(4A) A1D4C6.3
NetA1C6_P$9: A1C6.P$9(5A) A1D5C6.3
NetA1C6_P$11: A1C6.P$11(6A) A1D6C6.3
NetA1C7_P$1: A1C7.P$1(1A) A1D1C7.3
NetA1C7_P$2: A1C7.P$2(1B) A1C7.P$4(2B) A1C7.P$6(3B) A1C7.P$8(4B) A1C7.P$10(5B) A1C7.P$12(6B) A1D7C7.3
NetA1C7_P$3: A1C7.P$3(2A) A1D2C7.3
NetA1C7_P$5: A1C7.P$5(3A) A1D3C7.3
NetA1C7_P$7: A1C7.P$7(4A) A1D4C7.3
NetA1C7_P$9: A1C7.P$9(5A) A1D5C7.3
NetA1C7_P$11: A1C7.P$11(6A) A1D6C7.3
NetA1C8_P$1: A1C8.P$1(1A) A1D1C8.3
NetA1C8_P$2: A1C8.P$2(1B) A1C8.P$4(2B) A1C8.P$6(3B) A1C8.P$8(4B) A1C8.P$10(5B) A1C8.P$12(6B) A1D7C8.3
NetA1C8_P$3: A1C8.P$3(2A) A1D2C8.3
NetA1C8_P$5: A1C8.P$5(3A) A1D3C8.3
NetA1C8_P$7: A1C8.P$7(4A) A1D4C8.3
NetA1C8_P$9: A1C8.P$9(5A) A1D5C8.3
NetA1C8_P$11: A1C8.P$11(6A) A1D6C8.3

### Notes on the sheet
- Refreshable Braille Display
- Array 1 Braille Cell Array Schematic
- 3
- 6
- 1.0

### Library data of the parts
A1C1-A1C8 = BRAILLE-6: GateName_1: G$1
A1D1C1-A1D1C8 A1D2C1-A1D2C8 A1D3C1-A1D3C8 A1D4C1-A1D4C8 A1D5C1-A1D5C8 A1D6C1-A1D6C8 A1D7C1-A1D7C8 = CMP-12791-000024-1: DIODE ARRAY GP 85V 75MA SOT523; Manufacturer: Diodes Inc.; Capacitance: 1.5pF; Value: 1.5pF; Standoff Height: 0mm; Peak Reverse Current: 2uA; Max Surge Forward Current: 0.5A; Max Junction Temp: +150°C

## Sheet Array 2 Cell Driving Schematic.SchDoc
size A4; SheetNumber: 4; SheetTotal: 6
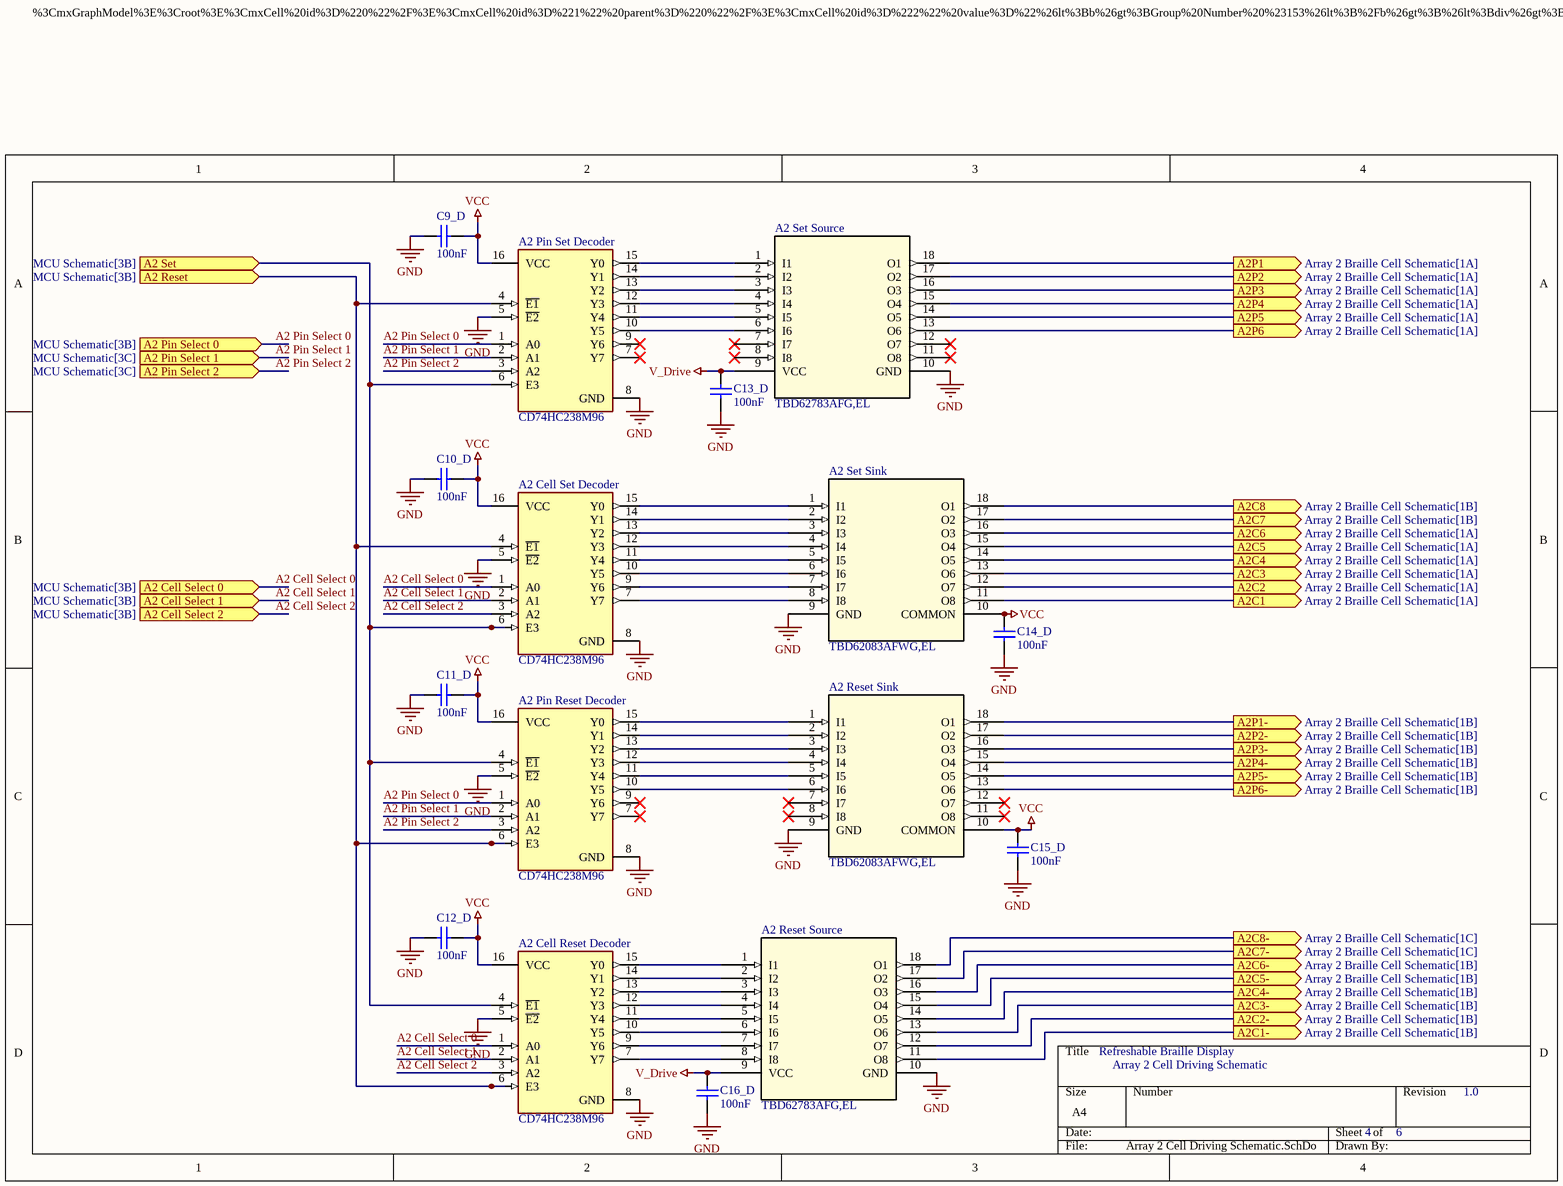
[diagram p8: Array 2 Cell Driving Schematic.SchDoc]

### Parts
A2_Cell_Reset_Decoder  CD74HC238M96  [FP-D0016A-MFG]
A2_Cell_Set_Decoder  CD74HC238M96  [FP-D0016A-MFG]
A2_Pin_Reset_Decoder  CD74HC238M96  [FP-D0016A-MFG]
A2_Pin_Set_Decoder  CD74HC238M96  [FP-D0016A-MFG]
A2_Reset_Sink  TBD62083AFWG,EL  [P-SOP18-0812-1p27-001_TOS]
A2_Reset_Source  TBD62783AFG,EL  [SOP18-P-375-1p27_TOS]
A2_Set_Sink  TBD62083AFWG,EL  [P-SOP18-0812-1p27-001_TOS]
A2_Set_Source  TBD62783AFG,EL  [SOP18-P-375-1p27_TOS]
C9_D  100nF  [CAPC0805(2012)100_M]
C10_D  100nF  [CAPC0805(2012)100_M]
C11_D  100nF  [CAPC0805(2012)100_M]
C12_D  100nF  [CAPC0805(2012)100_M]
C13_D  100nF  [CAPC0805(2012)100_M]
C14_D  100nF  [CAPC0805(2012)100_M]
C15_D  100nF  [CAPC0805(2012)100_M]
C16_D  100nF  [CAPC0805(2012)100_M]

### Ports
A2 Cell Select 0 (in, see MCU Schematic[3B]), A2 Cell Select 1 (in, see MCU Schematic[3B]), A2 Cell Select 2 (in, see MCU Schematic[3B]), A2 Pin Select 0 (in, see MCU Schematic[3B]), A2 Pin Select 1 (in, see MCU Schematic[3C]), A2 Pin Select 2 (in, see MCU Schematic[3C]), A2 Reset (in, see MCU Schematic[3B]), A2 Set (in, see MCU Schematic[3B]), A2C1 (out, see Array 2 Braille Cell Schematic[1A]), A2C1- (out, see Array 2 Braille Cell Schematic[1B]), A2C2 (out, see Array 2 Braille Cell Schematic[1A]), A2C2- (out, see Array 2 Braille Cell Schematic[1B]), A2C3 (out, see Array 2 Braille Cell Schematic[1A]), A2C3- (out, see Array 2 Braille Cell Schematic[1B]), A2C4 (out, see Array 2 Braille Cell Schematic[1A]), A2C4- (out, see Array 2 Braille Cell Schematic[1B]), A2C5 (out, see Array 2 Braille Cell Schematic[1A]), A2C5- (out, see Array 2 Braille Cell Schematic[1B]), A2C6 (out, see Array 2 Braille Cell Schematic[1A]), A2C6- (out, see Array 2 Braille Cell Schematic[1B]), A2C7 (out, see Array 2 Braille Cell Schematic[1B]), A2C7- (out, see Array 2 Braille Cell Schematic[1C]), A2C8 (out, see Array 2 Braille Cell Schematic[1B]), A2C8- (out, see Array 2 Braille Cell Schematic[1C]), A2P1 (out, see Array 2 Braille Cell Schematic[1A]), A2P1- (out, see Array 2 Braille Cell Schematic[1B]), A2P2 (out, see Array 2 Braille Cell Schematic[1A]), A2P2- (out, see Array 2 Braille Cell Schematic[1B]), A2P3 (out, see Array 2 Braille Cell Schematic[1A]), A2P3- (out, see Array 2 Braille Cell Schematic[1B]), A2P4 (out, see Array 2 Braille Cell Schematic[1A]), A2P4- (out, see Array 2 Braille Cell Schematic[1B]), A2P5 (out, see Array 2 Braille Cell Schematic[1A]), A2P5- (out, see Array 2 Braille Cell Schematic[1B]), A2P6 (out, see Array 2 Braille Cell Schematic[1A]), A2P6- (out, see Array 2 Braille Cell Schematic[1B])

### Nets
GND: A2_Cell_Reset_Decoder.5(~{E2}) A2_Cell_Reset_Decoder.8(GND) A2_Cell_Set_Decoder.5(~{E2}) A2_Cell_Set_Decoder.8(GND) A2_Pin_Reset_Decoder.5(~{E2}) A2_Pin_Reset_Decoder.8(GND) A2_Pin_Set_Decoder.5(~{E2}) A2_Pin_Set_Decoder.8(GND) A2_Reset_Sink.9(GND) A2_Reset_Source.10(GND) A2_Set_Sink.9(GND) A2_Set_Source.10(GND) C9_D.2 C10_D.2 C11_D.2 C12_D.2 C13_D.1 C14_D.1 C15_D.1 C16_D.1
V_Drive: A2_Reset_Source.9(VCC) A2_Set_Source.9(VCC) C13_D.2 C16_D.2
VCC: A2_Cell_Reset_Decoder.16(VCC) A2_Cell_Set_Decoder.16(VCC) A2_Pin_Reset_Decoder.16(VCC) A2_Pin_Set_Decoder.16(VCC) A2_Reset_Sink.10(COMMON) A2_Set_Sink.10(COMMON) C9_D.1 C10_D.1 C11_D.1 C12_D.1 C14_D.2 C15_D.2
A2 Cell1: A2_Set_Sink.11(O8) ; port A2C1
A2 Cell1 Reset: A2_Reset_Source.11(O8) ; port A2C1-
A2 Cell2: A2_Set_Sink.12(O7) ; port A2C2
A2 Cell2 Reset: A2_Reset_Source.12(O7) ; port A2C2-
A2 Cell3: A2_Set_Sink.13(O6) ; port A2C3
A2 Cell3 Reset: A2_Reset_Source.13(O6) ; port A2C3-
A2 Cell4: A2_Set_Sink.14(O5) ; port A2C4
A2 Cell4 Reset: A2_Reset_Source.14(O5) ; port A2C4-
A2 Cell5: A2_Set_Sink.15(O4) ; port A2C5
A2 Cell5 Reset: A2_Reset_Source.15(O4) ; port A2C5-
A2 Cell6: A2_Set_Sink.16(O3) ; port A2C6
A2 Cell6 Reset: A2_Reset_Source.16(O3) ; port A2C6-
A2 Cell7: A2_Set_Sink.17(O2) ; port A2C7
A2 Cell7 Reset: A2_Reset_Source.17(O2) ; port A2C7-
A2 Cell8: A2_Set_Sink.18(O1) ; port A2C8
A2 Cell8 Reset: A2_Reset_Source.18(O1) ; port A2C8-
A2 Cell Select 0: A2_Cell_Reset_Decoder.1(A0) A2_Cell_Set_Decoder.1(A0) ; port A2 Cell Select 0
A2 Cell Select 1: A2_Cell_Reset_Decoder.2(A1) A2_Cell_Set_Decoder.2(A1) ; port A2 Cell Select 1
A2 Cell Select 2: A2_Cell_Reset_Decoder.3(A2) A2_Cell_Set_Decoder.3(A2) ; port A2 Cell Select 2
A2 Pin1: A2_Set_Source.18(O1) ; port A2P1
A2 Pin1 Reset: A2_Reset_Sink.18(O1) ; port A2P1-
A2 Pin2: A2_Set_Source.17(O2) ; port A2P2
A2 Pin2 Reset: A2_Reset_Sink.17(O2) ; port A2P2-
A2 Pin3: A2_Set_Source.16(O3) ; port A2P3
A2 Pin3 Reset: A2_Reset_Sink.16(O3) ; port A2P3-
A2 Pin4: A2_Set_Source.15(O4) ; port A2P4
A2 Pin4 Reset: A2_Reset_Sink.15(O4) ; port A2P4-
A2 Pin5: A2_Set_Source.14(O5) ; port A2P5
A2 Pin5 Reset: A2_Reset_Sink.14(O5) ; port A2P5-
A2 Pin6: A2_Set_Source.13(O6) ; port A2P6
A2 Pin6 Reset: A2_Reset_Sink.13(O6) ; port A2P6-
A2 Pin Select 0: A2_Pin_Reset_Decoder.1(A0) A2_Pin_Set_Decoder.1(A0) ; port A2 Pin Select 0
A2 Pin Select 1: A2_Pin_Reset_Decoder.2(A1) A2_Pin_Set_Decoder.2(A1) ; port A2 Pin Select 1
A2 Pin Select 2: A2_Pin_Reset_Decoder.3(A2) A2_Pin_Set_Decoder.3(A2) ; port A2 Pin Select 2
NetA2_Cell_Reset_Decoder_4: A2_Cell_Reset_Decoder.4(~{E1}) A2_Cell_Set_Decoder.6(E3) A2_Pin_Reset_Decoder.4(~{E1}) A2_Pin_Set_Decoder.6(E3) ; port A2 Set
NetA2_Cell_Reset_Decoder_6: A2_Cell_Reset_Decoder.6(E3) A2_Cell_Set_Decoder.4(~{E1}) A2_Pin_Reset_Decoder.6(E3) A2_Pin_Set_Decoder.4(~{E1}) ; port A2 Reset
NetA2_Cell_Reset_Decoder_7: A2_Cell_Reset_Decoder.7(Y7) A2_Reset_Source.8(I8)
NetA2_Cell_Reset_Decoder_9: A2_Cell_Reset_Decoder.9(Y6) A2_Reset_Source.7(I7)
NetA2_Cell_Reset_Decoder_10: A2_Cell_Reset_Decoder.10(Y5) A2_Reset_Source.6(I6)
NetA2_Cell_Reset_Decoder_11: A2_Cell_Reset_Decoder.11(Y4) A2_Reset_Source.5(I5)
NetA2_Cell_Reset_Decoder_12: A2_Cell_Reset_Decoder.12(Y3) A2_Reset_Source.4(I4)
NetA2_Cell_Reset_Decoder_13: A2_Cell_Reset_Decoder.13(Y2) A2_Reset_Source.3(I3)
NetA2_Cell_Reset_Decoder_14: A2_Cell_Reset_Decoder.14(Y1) A2_Reset_Source.2(I2)
NetA2_Cell_Reset_Decoder_15: A2_Cell_Reset_Decoder.15(Y0) A2_Reset_Source.1(I1)
NetA2_Cell_Set_Decoder_7: A2_Cell_Set_Decoder.7(Y7) A2_Set_Sink.8(I8)
NetA2_Cell_Set_Decoder_9: A2_Cell_Set_Decoder.9(Y6) A2_Set_Sink.7(I7)
NetA2_Cell_Set_Decoder_10: A2_Cell_Set_Decoder.10(Y5) A2_Set_Sink.6(I6)
NetA2_Cell_Set_Decoder_11: A2_Cell_Set_Decoder.11(Y4) A2_Set_Sink.5(I5)
NetA2_Cell_Set_Decoder_12: A2_Cell_Set_Decoder.12(Y3) A2_Set_Sink.4(I4)
NetA2_Cell_Set_Decoder_13: A2_Cell_Set_Decoder.13(Y2) A2_Set_Sink.3(I3)
NetA2_Cell_Set_Decoder_14: A2_Cell_Set_Decoder.14(Y1) A2_Set_Sink.2(I2)
NetA2_Cell_Set_Decoder_15: A2_Cell_Set_Decoder.15(Y0) A2_Set_Sink.1(I1)
NetA2_Pin_Reset_Decoder_10: A2_Pin_Reset_Decoder.10(Y5) A2_Reset_Sink.6(I6)
NetA2_Pin_Reset_Decoder_11: A2_Pin_Reset_Decoder.11(Y4) A2_Reset_Sink.5(I5)
NetA2_Pin_Reset_Decoder_12: A2_Pin_Reset_Decoder.12(Y3) A2_Reset_Sink.4(I4)
NetA2_Pin_Reset_Decoder_13: A2_Pin_Reset_Decoder.13(Y2) A2_Reset_Sink.3(I3)
NetA2_Pin_Reset_Decoder_14: A2_Pin_Reset_Decoder.14(Y1) A2_Reset_Sink.2(I2)
NetA2_Pin_Reset_Decoder_15: A2_Pin_Reset_Decoder.15(Y0) A2_Reset_Sink.1(I1)
NetA2_Pin_Set_Decoder_10: A2_Pin_Set_Decoder.10(Y5) A2_Set_Source.6(I6)
NetA2_Pin_Set_Decoder_11: A2_Pin_Set_Decoder.11(Y4) A2_Set_Source.5(I5)
NetA2_Pin_Set_Decoder_12: A2_Pin_Set_Decoder.12(Y3) A2_Set_Source.4(I4)
NetA2_Pin_Set_Decoder_13: A2_Pin_Set_Decoder.13(Y2) A2_Set_Source.3(I3)
NetA2_Pin_Set_Decoder_14: A2_Pin_Set_Decoder.14(Y1) A2_Set_Source.2(I2)
NetA2_Pin_Set_Decoder_15: A2_Pin_Set_Decoder.15(Y0) A2_Set_Source.1(I1)

Not connected (* = marked no-connect by the designer): A2_Pin_Reset_Decoder 7(Y7)* 9(Y6)*; A2_Pin_Set_Decoder 7(Y7)* 9(Y6)*; A2_Reset_Sink 7(I7)* 8(I8)* 11(O8)* 12(O7)*; A2_Set_Source 7(I7)* 8(I8)* 11(O8)* 12(O7)*

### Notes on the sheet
- %3CmxGraphModel%3E%3Croot%3E%3CmxCell%20id%3D%220%22%2F%3E%3CmxCell%20id%3D%221%22%20parent%3D%220%22%2F%3E%3CmxCell%20id%3D%222%22%20value%3D%22%26lt%3Bb%26gt%3BGroup%20Number%20%23153%26lt%3B%2Fb%26gt%3B%26lt%3Bdiv%26gt%3B%26lt%3Bb%26gt%3B%26lt%3Bbr%26gt%3B%26lt%3B%2Fb%26gt%3B%26lt%3Bdiv%26gt%3B%26lt%3Bspan%20style%3D%26quot%3Bbackground-color%3A%20transparent%3B%20color%3A%20light-dark(rgb(0%2C%200%2C%200)%2C%20rgb(255%2C%20255%2C%20255))%3B%26quot%3B%26gt%3BAlbert%20Li%201661902%26lt%3B%2Fspan%26gt%3B%26lt%3B%2Fdiv%26gt%3B%26lt%3Bdiv%26gt%3BWiktoria%20Klimczak%201778458%26lt%3B%2Fdiv%26gt%3B%26lt%3Bdiv%26gt%3BVivien%20Cen%201702106%26lt%3B%2Fdiv%26gt%3B%26lt%3Bdiv%26gt%3BCatherine%20Milliken%201614973%26lt%3B%2Fdiv%26gt%3B%26lt%3Bdiv%26gt%3BKatharine%20Zhong%201707425%26lt%3B%2Fdiv%26gt%3B%26lt%3B%2Fdiv%26gt%3B%22%20style%3D%22rounded%3D0%3BwhiteSpace%3Dwrap%3Bhtml%3D1%3Balign%3Dleft%3B%22%20vertex%3D%221%22%20parent%3D%221%22%3E%3CmxGeometry%20x%3D%22-1770%22%20y%3D%2228.5%22%20width%3D%22310%22%20height%3D%22110%22%20as%3D%22geometry%22%2F%3E%3C%2FmxCell%3E%3C%2Froot%3E%3C%2FmxGraphModel%3E
- Refreshable Braille Display
- Array 2 Cell Driving Schematic
- 4
- 6
- 1.0

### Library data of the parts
A2_Cell_Reset_Decoder A2_Cell_Set_Decoder A2_Pin_Reset_Decoder A2_Pin_Set_Decoder = CMP-1633-00102-3: as A1_Cell_Reset_Decoder on sheet Array 1 Cell Driving Schematic
A2_Reset_Sink A2_Set_Sink = TBD62083AFWG,EL: as A1_Reset_Sink on sheet Array 1 Cell Driving Schematic
A2_Reset_Source A2_Set_Source = TBD62783AFG,EL: as A1_Reset_Source on sheet Array 1 Cell Driving Schematic
C9_D C10_D C11_D C12_D C13_D C14_D C15_D C16_D = CMP-1036-04393-1: as C1_MCU on sheet MCU Schematic

## Sheet Array 2 Braille Cell Schematic.SchDoc
size D; SheetNumber: 5; SheetTotal: 6
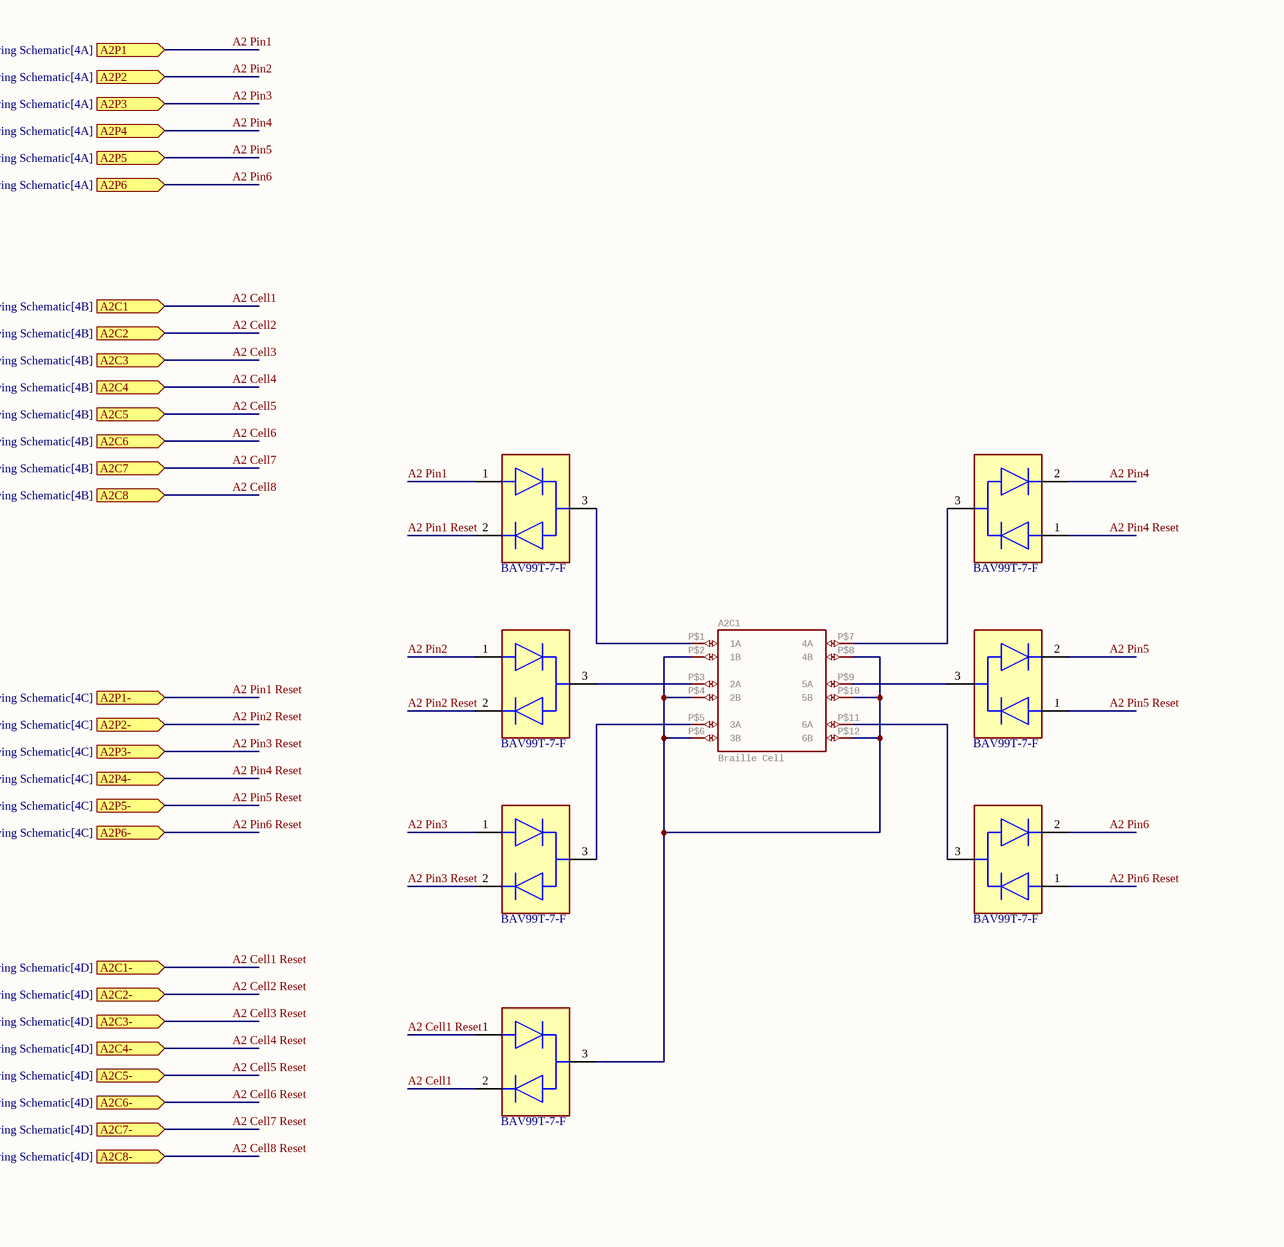
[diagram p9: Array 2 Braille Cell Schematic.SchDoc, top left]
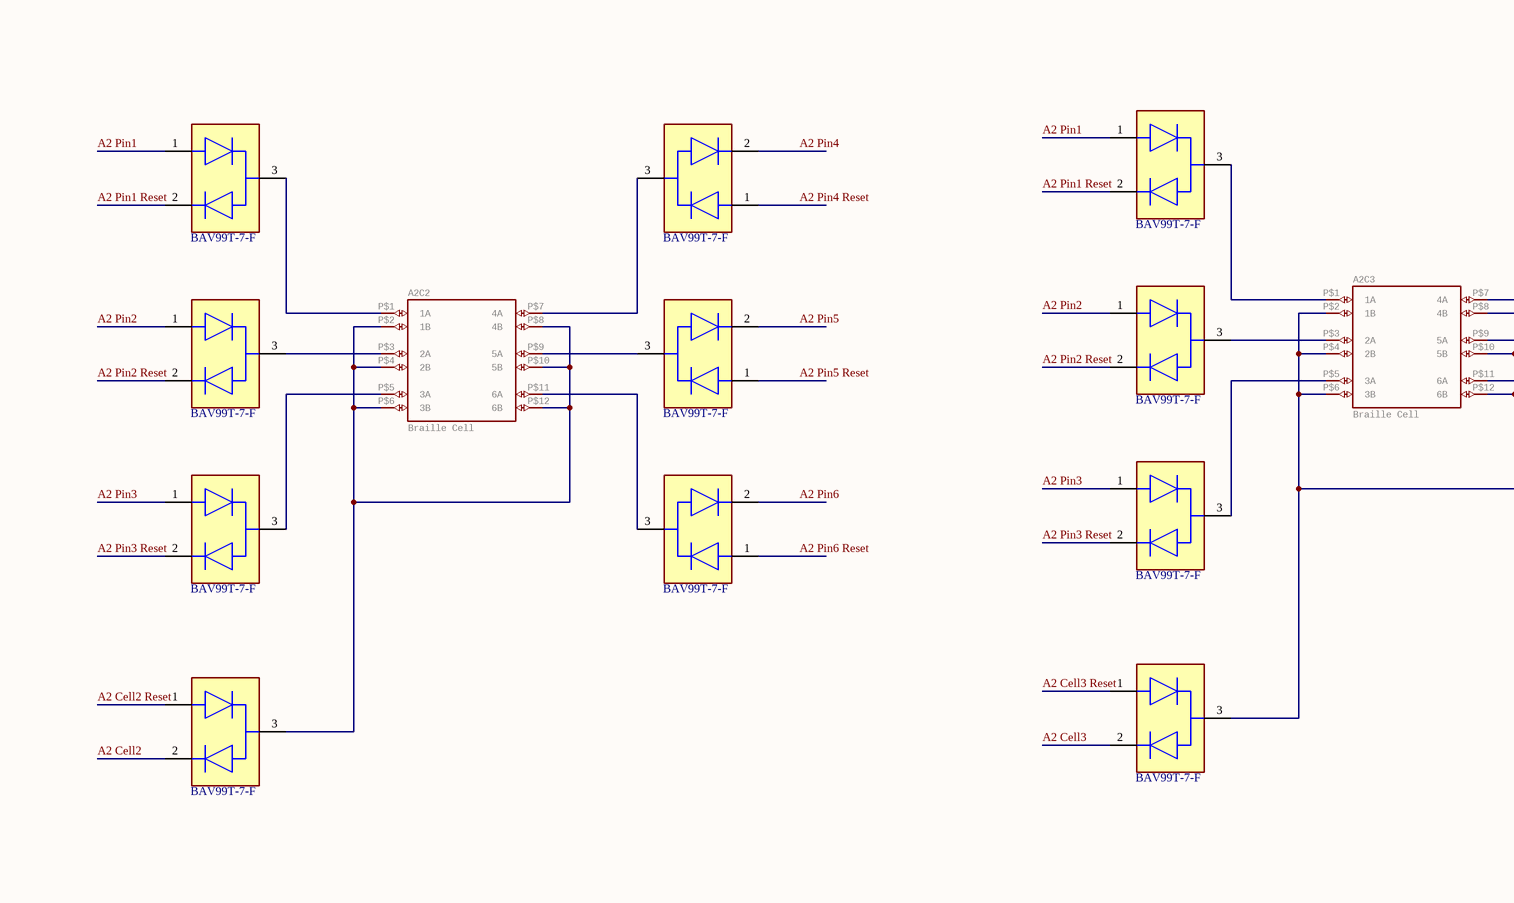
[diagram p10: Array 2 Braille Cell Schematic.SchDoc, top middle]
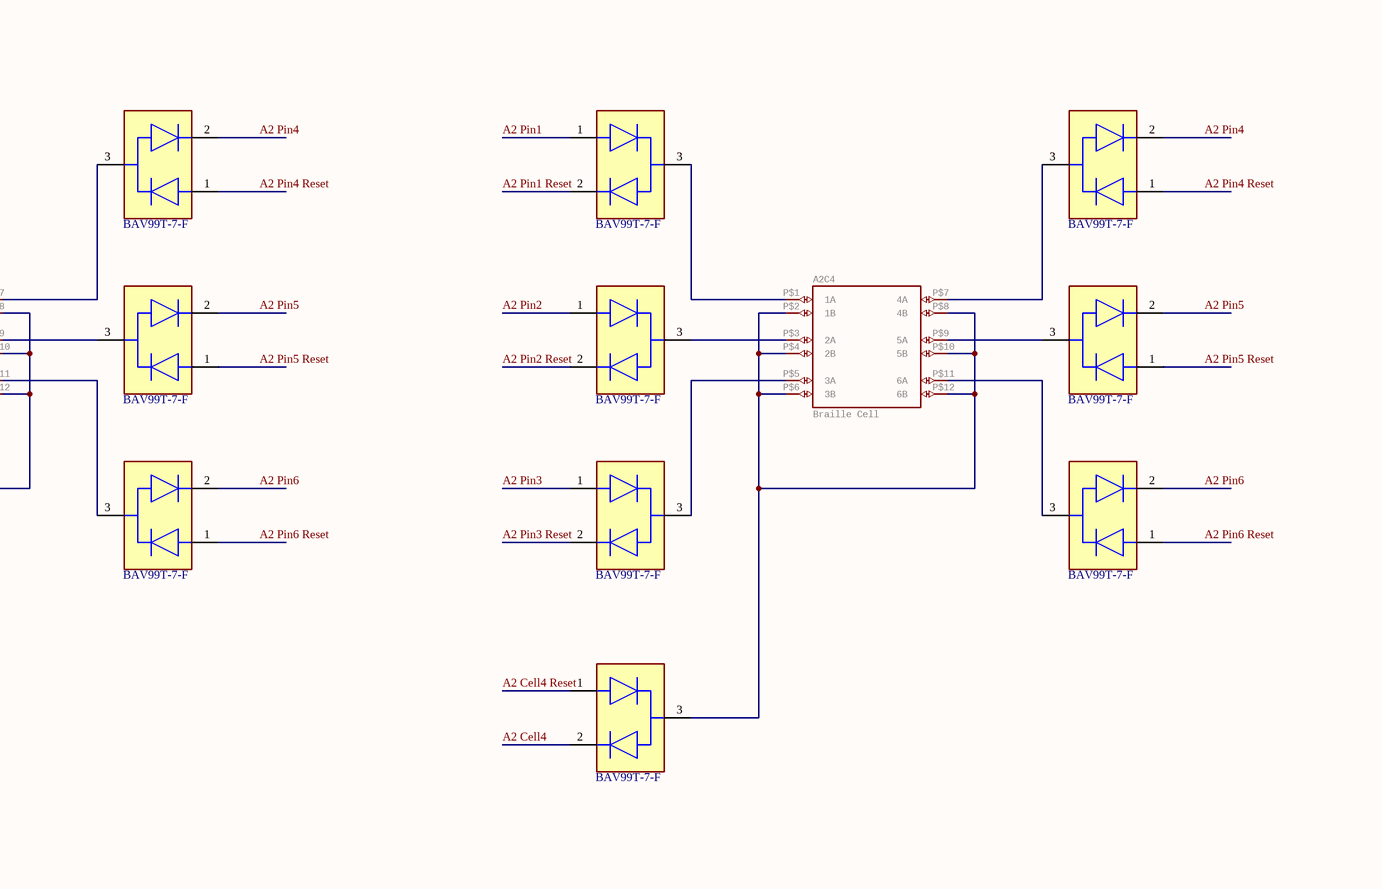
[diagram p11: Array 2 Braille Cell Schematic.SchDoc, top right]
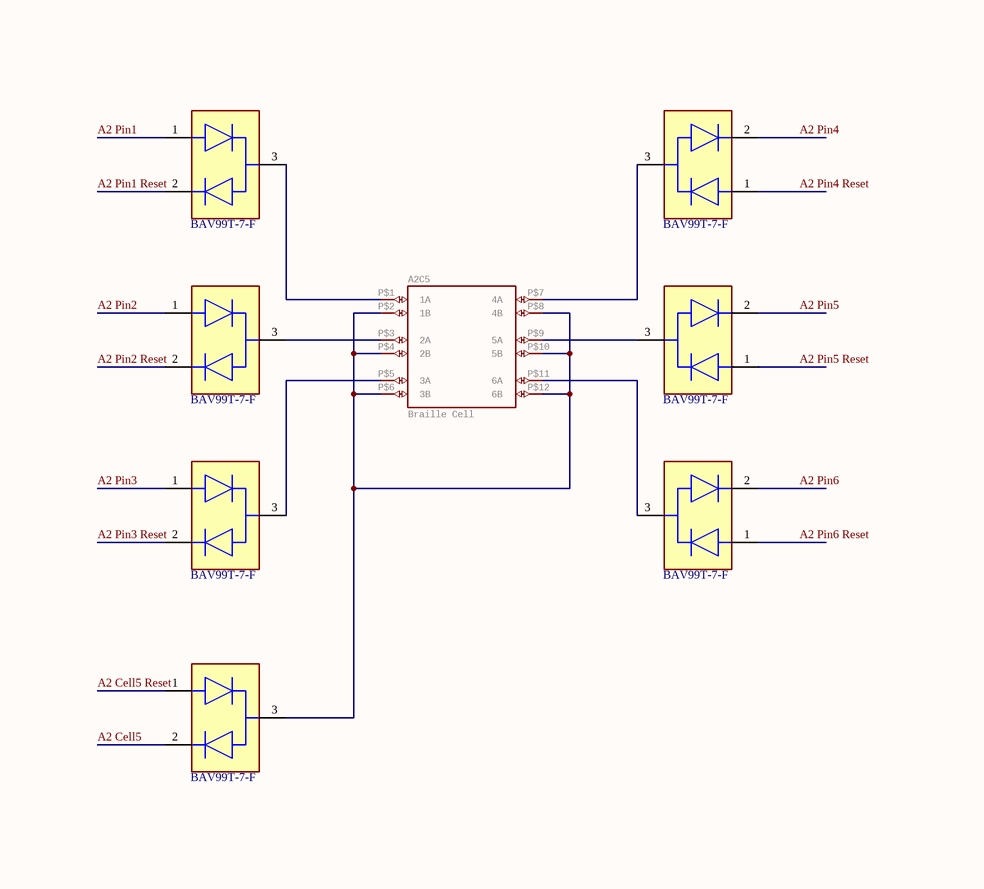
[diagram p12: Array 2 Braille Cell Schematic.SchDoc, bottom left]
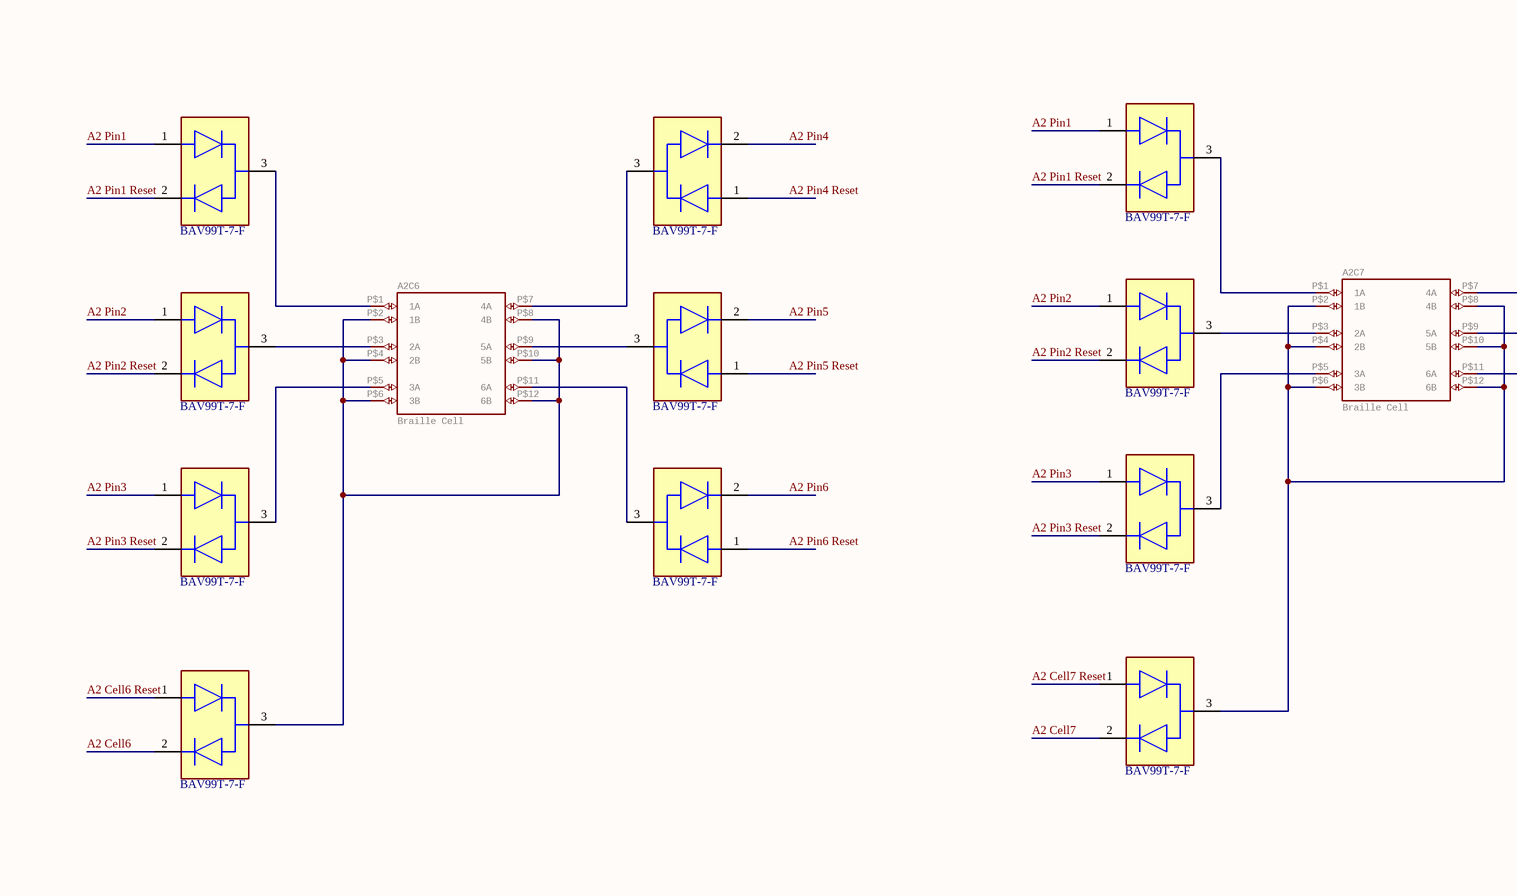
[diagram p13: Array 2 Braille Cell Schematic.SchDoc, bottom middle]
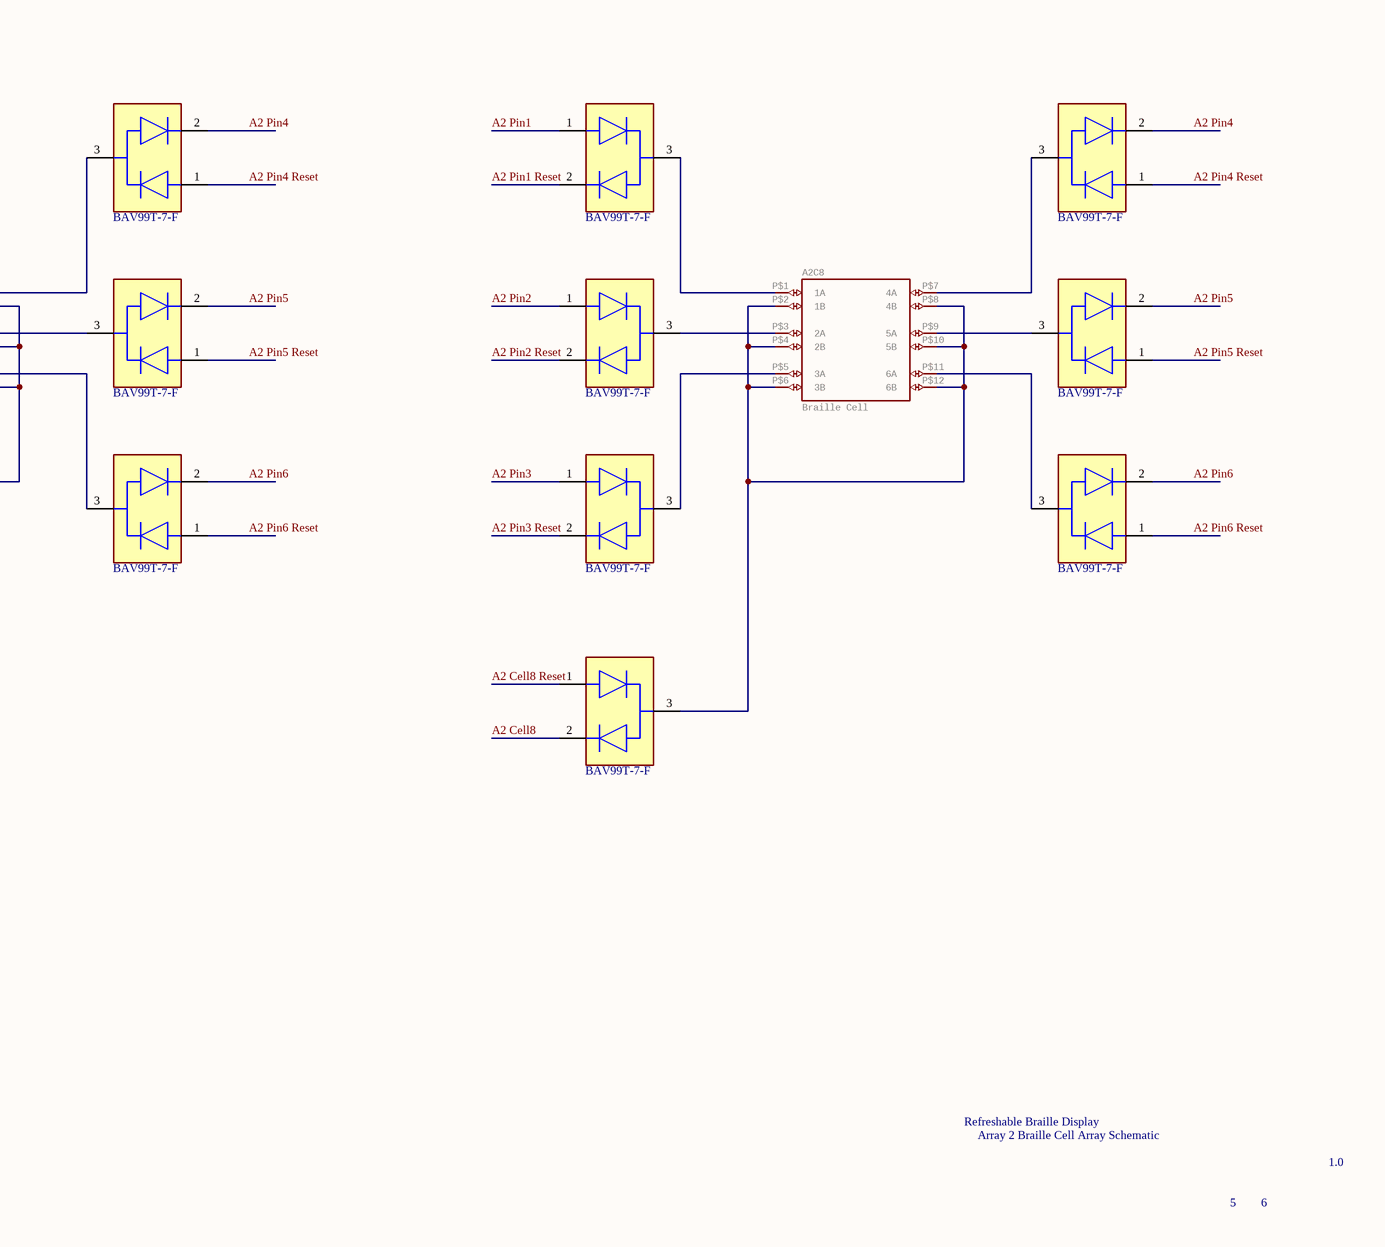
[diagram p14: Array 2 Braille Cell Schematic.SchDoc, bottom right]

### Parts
A2C1  Braille Cell  [BRAILLE-6]
A2C2  Braille Cell  [BRAILLE-6]
A2C3  Braille Cell  [BRAILLE-6]
A2C4  Braille Cell  [BRAILLE-6]
A2C5  Braille Cell  [BRAILLE-6]
A2C6  Braille Cell  [BRAILLE-6]
A2C7  Braille Cell  [BRAILLE-6]
A2C8  Braille Cell  [BRAILLE-6]
A2D1C1  BAV99T-7-F  [FP-SOT523-MFG]
A2D1C2  BAV99T-7-F  [FP-SOT523-MFG]
A2D1C3  BAV99T-7-F  [FP-SOT523-MFG]
A2D1C4  BAV99T-7-F  [FP-SOT523-MFG]
A2D1C5  BAV99T-7-F  [FP-SOT523-MFG]
A2D1C6  BAV99T-7-F  [FP-SOT523-MFG]
A2D1C7  BAV99T-7-F  [FP-SOT523-MFG]
A2D1C8  BAV99T-7-F  [FP-SOT523-MFG]
A2D2C1  BAV99T-7-F  [FP-SOT523-MFG]
A2D2C2  BAV99T-7-F  [FP-SOT523-MFG]
A2D2C3  BAV99T-7-F  [FP-SOT523-MFG]
A2D2C4  BAV99T-7-F  [FP-SOT523-MFG]
A2D2C5  BAV99T-7-F  [FP-SOT523-MFG]
A2D2C6  BAV99T-7-F  [FP-SOT523-MFG]
A2D2C7  BAV99T-7-F  [FP-SOT523-MFG]
A2D2C8  BAV99T-7-F  [FP-SOT523-MFG]
A2D3C1  BAV99T-7-F  [FP-SOT523-MFG]
A2D3C2  BAV99T-7-F  [FP-SOT523-MFG]
A2D3C3  BAV99T-7-F  [FP-SOT523-MFG]
A2D3C4  BAV99T-7-F  [FP-SOT523-MFG]
A2D3C5  BAV99T-7-F  [FP-SOT523-MFG]
A2D3C6  BAV99T-7-F  [FP-SOT523-MFG]
A2D3C7  BAV99T-7-F  [FP-SOT523-MFG]
A2D3C8  BAV99T-7-F  [FP-SOT523-MFG]
A2D4C1  BAV99T-7-F  [FP-SOT523-MFG]
A2D4C2  BAV99T-7-F  [FP-SOT523-MFG]
A2D4C3  BAV99T-7-F  [FP-SOT523-MFG]
A2D4C4  BAV99T-7-F  [FP-SOT523-MFG]
A2D4C5  BAV99T-7-F  [FP-SOT523-MFG]
A2D4C6  BAV99T-7-F  [FP-SOT523-MFG]
A2D4C7  BAV99T-7-F  [FP-SOT523-MFG]
A2D4C8  BAV99T-7-F  [FP-SOT523-MFG]
A2D5C1  BAV99T-7-F  [FP-SOT523-MFG]
A2D5C2  BAV99T-7-F  [FP-SOT523-MFG]
A2D5C3  BAV99T-7-F  [FP-SOT523-MFG]
A2D5C4  BAV99T-7-F  [FP-SOT523-MFG]
A2D5C5  BAV99T-7-F  [FP-SOT523-MFG]
A2D5C6  BAV99T-7-F  [FP-SOT523-MFG]
A2D5C7  BAV99T-7-F  [FP-SOT523-MFG]
A2D5C8  BAV99T-7-F  [FP-SOT523-MFG]
A2D6C1  BAV99T-7-F  [FP-SOT523-MFG]
A2D6C2  BAV99T-7-F  [FP-SOT523-MFG]
A2D6C3  BAV99T-7-F  [FP-SOT523-MFG]
A2D6C4  BAV99T-7-F  [FP-SOT523-MFG]
A2D6C5  BAV99T-7-F  [FP-SOT523-MFG]
A2D6C6  BAV99T-7-F  [FP-SOT523-MFG]
A2D6C7  BAV99T-7-F  [FP-SOT523-MFG]
A2D6C8  BAV99T-7-F  [FP-SOT523-MFG]
A2D7C1  BAV99T-7-F  [FP-SOT523-MFG]
A2D7C2  BAV99T-7-F  [FP-SOT523-MFG]
A2D7C3  BAV99T-7-F  [FP-SOT523-MFG]
A2D7C4  BAV99T-7-F  [FP-SOT523-MFG]
A2D7C5  BAV99T-7-F  [FP-SOT523-MFG]
A2D7C6  BAV99T-7-F  [FP-SOT523-MFG]
A2D7C7  BAV99T-7-F  [FP-SOT523-MFG]
A2D7C8  BAV99T-7-F  [FP-SOT523-MFG]

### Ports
A2C1 (in, see Array 2 Cell Driving Schematic[4B]), A2C1- (in, see Array 2 Cell Driving Schematic[4D]), A2C2 (in, see Array 2 Cell Driving Schematic[4B]), A2C2- (in, see Array 2 Cell Driving Schematic[4D]), A2C3 (in, see Array 2 Cell Driving Schematic[4B]), A2C3- (in, see Array 2 Cell Driving Schematic[4D]), A2C4 (in, see Array 2 Cell Driving Schematic[4B]), A2C4- (in, see Array 2 Cell Driving Schematic[4D]), A2C5 (in, see Array 2 Cell Driving Schematic[4B]), A2C5- (in, see Array 2 Cell Driving Schematic[4D]), A2C6 (in, see Array 2 Cell Driving Schematic[4B]), A2C6- (in, see Array 2 Cell Driving Schematic[4D]), A2C7 (in, see Array 2 Cell Driving Schematic[4B]), A2C7- (in, see Array 2 Cell Driving Schematic[4D]), A2C8 (in, see Array 2 Cell Driving Schematic[4B]), A2C8- (in, see Array 2 Cell Driving Schematic[4D]), A2P1 (in, see Array 2 Cell Driving Schematic[4A]), A2P1- (in, see Array 2 Cell Driving Schematic[4C]), A2P2 (in, see Array 2 Cell Driving Schematic[4A]), A2P2- (in, see Array 2 Cell Driving Schematic[4C]), A2P3 (in, see Array 2 Cell Driving Schematic[4A]), A2P3- (in, see Array 2 Cell Driving Schematic[4C]), A2P4 (in, see Array 2 Cell Driving Schematic[4A]), A2P4- (in, see Array 2 Cell Driving Schematic[4C]), A2P5 (in, see Array 2 Cell Driving Schematic[4A]), A2P5- (in, see Array 2 Cell Driving Schematic[4C]), A2P6 (in, see Array 2 Cell Driving Schematic[4A]), A2P6- (in, see Array 2 Cell Driving Schematic[4C])

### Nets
A2 Cell1: A2D7C1.2 ; port A2C1
A2 Cell1 Reset: A2D7C1.1 ; port A2C1-
A2 Cell2: A2D7C2.2 ; port A2C2
A2 Cell2 Reset: A2D7C2.1 ; port A2C2-
A2 Cell3: A2D7C3.2 ; port A2C3
A2 Cell3 Reset: A2D7C3.1 ; port A2C3-
A2 Cell4: A2D7C4.2 ; port A2C4
A2 Cell4 Reset: A2D7C4.1 ; port A2C4-
A2 Cell5: A2D7C5.2 ; port A2C5
A2 Cell5 Reset: A2D7C5.1 ; port A2C5-
A2 Cell6: A2D7C6.2 ; port A2C6
A2 Cell6 Reset: A2D7C6.1 ; port A2C6-
A2 Cell7: A2D7C7.2 ; port A2C7
A2 Cell7 Reset: A2D7C7.1 ; port A2C7-
A2 Cell8: A2D7C8.2 ; port A2C8
A2 Cell8 Reset: A2D7C8.1 ; port A2C8-
A2 Pin1: A2D1C1.1 A2D1C2.1 A2D1C3.1 A2D1C4.1 A2D1C5.1 A2D1C6.1 A2D1C7.1 A2D1C8.1 ; port A2P1
A2 Pin1 Reset: A2D1C1.2 A2D1C2.2 A2D1C3.2 A2D1C4.2 A2D1C5.2 A2D1C6.2 A2D1C7.2 A2D1C8.2 ; port A2P1-
A2 Pin2: A2D2C1.1 A2D2C2.1 A2D2C3.1 A2D2C4.1 A2D2C5.1 A2D2C6.1 A2D2C7.1 A2D2C8.1 ; port A2P2
A2 Pin2 Reset: A2D2C1.2 A2D2C2.2 A2D2C3.2 A2D2C4.2 A2D2C5.2 A2D2C6.2 A2D2C7.2 A2D2C8.2 ; port A2P2-
A2 Pin3: A2D3C1.1 A2D3C2.1 A2D3C3.1 A2D3C4.1 A2D3C5.1 A2D3C6.1 A2D3C7.1 A2D3C8.1 ; port A2P3
A2 Pin3 Reset: A2D3C1.2 A2D3C2.2 A2D3C3.2 A2D3C4.2 A2D3C5.2 A2D3C6.2 A2D3C7.2 A2D3C8.2 ; port A2P3-
A2 Pin4: A2D4C1.2 A2D4C2.2 A2D4C3.2 A2D4C4.2 A2D4C5.2 A2D4C6.2 A2D4C7.2 A2D4C8.2 ; port A2P4
A2 Pin4 Reset: A2D4C1.1 A2D4C2.1 A2D4C3.1 A2D4C4.1 A2D4C5.1 A2D4C6.1 A2D4C7.1 A2D4C8.1 ; port A2P4-
A2 Pin5: A2D5C1.2 A2D5C2.2 A2D5C3.2 A2D5C4.2 A2D5C5.2 A2D5C6.2 A2D5C7.2 A2D5C8.2 ; port A2P5
A2 Pin5 Reset: A2D5C1.1 A2D5C2.1 A2D5C3.1 A2D5C4.1 A2D5C5.1 A2D5C6.1 A2D5C7.1 A2D5C8.1 ; port A2P5-
A2 Pin6: A2D6C1.2 A2D6C2.2 A2D6C3.2 A2D6C4.2 A2D6C5.2 A2D6C6.2 A2D6C7.2 A2D6C8.2 ; port A2P6
A2 Pin6 Reset: A2D6C1.1 A2D6C2.1 A2D6C3.1 A2D6C4.1 A2D6C5.1 A2D6C6.1 A2D6C7.1 A2D6C8.1 ; port A2P6-
NetA2C1_P$1: A2C1.P$1(1A) A2D1C1.3
NetA2C1_P$2: A2C1.P$2(1B) A2C1.P$4(2B) A2C1.P$6(3B) A2C1.P$8(4B) A2C1.P$10(5B) A2C1.P$12(6B) A2D7C1.3
NetA2C1_P$3: A2C1.P$3(2A) A2D2C1.3
NetA2C1_P$5: A2C1.P$5(3A) A2D3C1.3
NetA2C1_P$7: A2C1.P$7(4A) A2D4C1.3
NetA2C1_P$9: A2C1.P$9(5A) A2D5C1.3
NetA2C1_P$11: A2C1.P$11(6A) A2D6C1.3
NetA2C2_P$1: A2C2.P$1(1A) A2D1C2.3
NetA2C2_P$2: A2C2.P$2(1B) A2C2.P$4(2B) A2C2.P$6(3B) A2C2.P$8(4B) A2C2.P$10(5B) A2C2.P$12(6B) A2D7C2.3
NetA2C2_P$3: A2C2.P$3(2A) A2D2C2.3
NetA2C2_P$5: A2C2.P$5(3A) A2D3C2.3
NetA2C2_P$7: A2C2.P$7(4A) A2D4C2.3
NetA2C2_P$9: A2C2.P$9(5A) A2D5C2.3
NetA2C2_P$11: A2C2.P$11(6A) A2D6C2.3
NetA2C3_P$1: A2C3.P$1(1A) A2D1C3.3
NetA2C3_P$2: A2C3.P$2(1B) A2C3.P$4(2B) A2C3.P$6(3B) A2C3.P$8(4B) A2C3.P$10(5B) A2C3.P$12(6B) A2D7C3.3
NetA2C3_P$3: A2C3.P$3(2A) A2D2C3.3
NetA2C3_P$5: A2C3.P$5(3A) A2D3C3.3
NetA2C3_P$7: A2C3.P$7(4A) A2D4C3.3
NetA2C3_P$9: A2C3.P$9(5A) A2D5C3.3
NetA2C3_P$11: A2C3.P$11(6A) A2D6C3.3
NetA2C4_P$1: A2C4.P$1(1A) A2D1C4.3
NetA2C4_P$2: A2C4.P$2(1B) A2C4.P$4(2B) A2C4.P$6(3B) A2C4.P$8(4B) A2C4.P$10(5B) A2C4.P$12(6B) A2D7C4.3
NetA2C4_P$3: A2C4.P$3(2A) A2D2C4.3
NetA2C4_P$5: A2C4.P$5(3A) A2D3C4.3
NetA2C4_P$7: A2C4.P$7(4A) A2D4C4.3
NetA2C4_P$9: A2C4.P$9(5A) A2D5C4.3
NetA2C4_P$11: A2C4.P$11(6A) A2D6C4.3
NetA2C5_P$1: A2C5.P$1(1A) A2D1C5.3
NetA2C5_P$2: A2C5.P$2(1B) A2C5.P$4(2B) A2C5.P$6(3B) A2C5.P$8(4B) A2C5.P$10(5B) A2C5.P$12(6B) A2D7C5.3
NetA2C5_P$3: A2C5.P$3(2A) A2D2C5.3
NetA2C5_P$5: A2C5.P$5(3A) A2D3C5.3
NetA2C5_P$7: A2C5.P$7(4A) A2D4C5.3
NetA2C5_P$9: A2C5.P$9(5A) A2D5C5.3
NetA2C5_P$11: A2C5.P$11(6A) A2D6C5.3
NetA2C6_P$1: A2C6.P$1(1A) A2D1C6.3
NetA2C6_P$2: A2C6.P$2(1B) A2C6.P$4(2B) A2C6.P$6(3B) A2C6.P$8(4B) A2C6.P$10(5B) A2C6.P$12(6B) A2D7C6.3
NetA2C6_P$3: A2C6.P$3(2A) A2D2C6.3
NetA2C6_P$5: A2C6.P$5(3A) A2D3C6.3
NetA2C6_P$7: A2C6.P$7(4A) A2D4C6.3
NetA2C6_P$9: A2C6.P$9(5A) A2D5C6.3
NetA2C6_P$11: A2C6.P$11(6A) A2D6C6.3
NetA2C7_P$1: A2C7.P$1(1A) A2D1C7.3
NetA2C7_P$2: A2C7.P$2(1B) A2C7.P$4(2B) A2C7.P$6(3B) A2C7.P$8(4B) A2C7.P$10(5B) A2C7.P$12(6B) A2D7C7.3
NetA2C7_P$3: A2C7.P$3(2A) A2D2C7.3
NetA2C7_P$5: A2C7.P$5(3A) A2D3C7.3
NetA2C7_P$7: A2C7.P$7(4A) A2D4C7.3
NetA2C7_P$9: A2C7.P$9(5A) A2D5C7.3
NetA2C7_P$11: A2C7.P$11(6A) A2D6C7.3
NetA2C8_P$1: A2C8.P$1(1A) A2D1C8.3
NetA2C8_P$2: A2C8.P$2(1B) A2C8.P$4(2B) A2C8.P$6(3B) A2C8.P$8(4B) A2C8.P$10(5B) A2C8.P$12(6B) A2D7C8.3
NetA2C8_P$3: A2C8.P$3(2A) A2D2C8.3
NetA2C8_P$5: A2C8.P$5(3A) A2D3C8.3
NetA2C8_P$7: A2C8.P$7(4A) A2D4C8.3
NetA2C8_P$9: A2C8.P$9(5A) A2D5C8.3
NetA2C8_P$11: A2C8.P$11(6A) A2D6C8.3

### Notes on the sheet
- Refreshable Braille Display
- Array 2 Braille Cell Array Schematic
- 5
- 6
- 1.0

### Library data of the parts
A2C1-A2C8 = BRAILLE-6: GateName_1: G$1
A2D1C1-A2D1C8 A2D2C1-A2D2C8 A2D3C1-A2D3C8 A2D4C1-A2D4C8 A2D5C1-A2D5C8 A2D6C1-A2D6C8 A2D7C1-A2D7C8 = CMP-12791-000024-1: as A1D1C1 on sheet Array 1 Braille Cell Schematic

## Sheet Power and Voltage Regulation Schematic.SchDoc
size A4; SheetNumber: 6; SheetTotal: 6
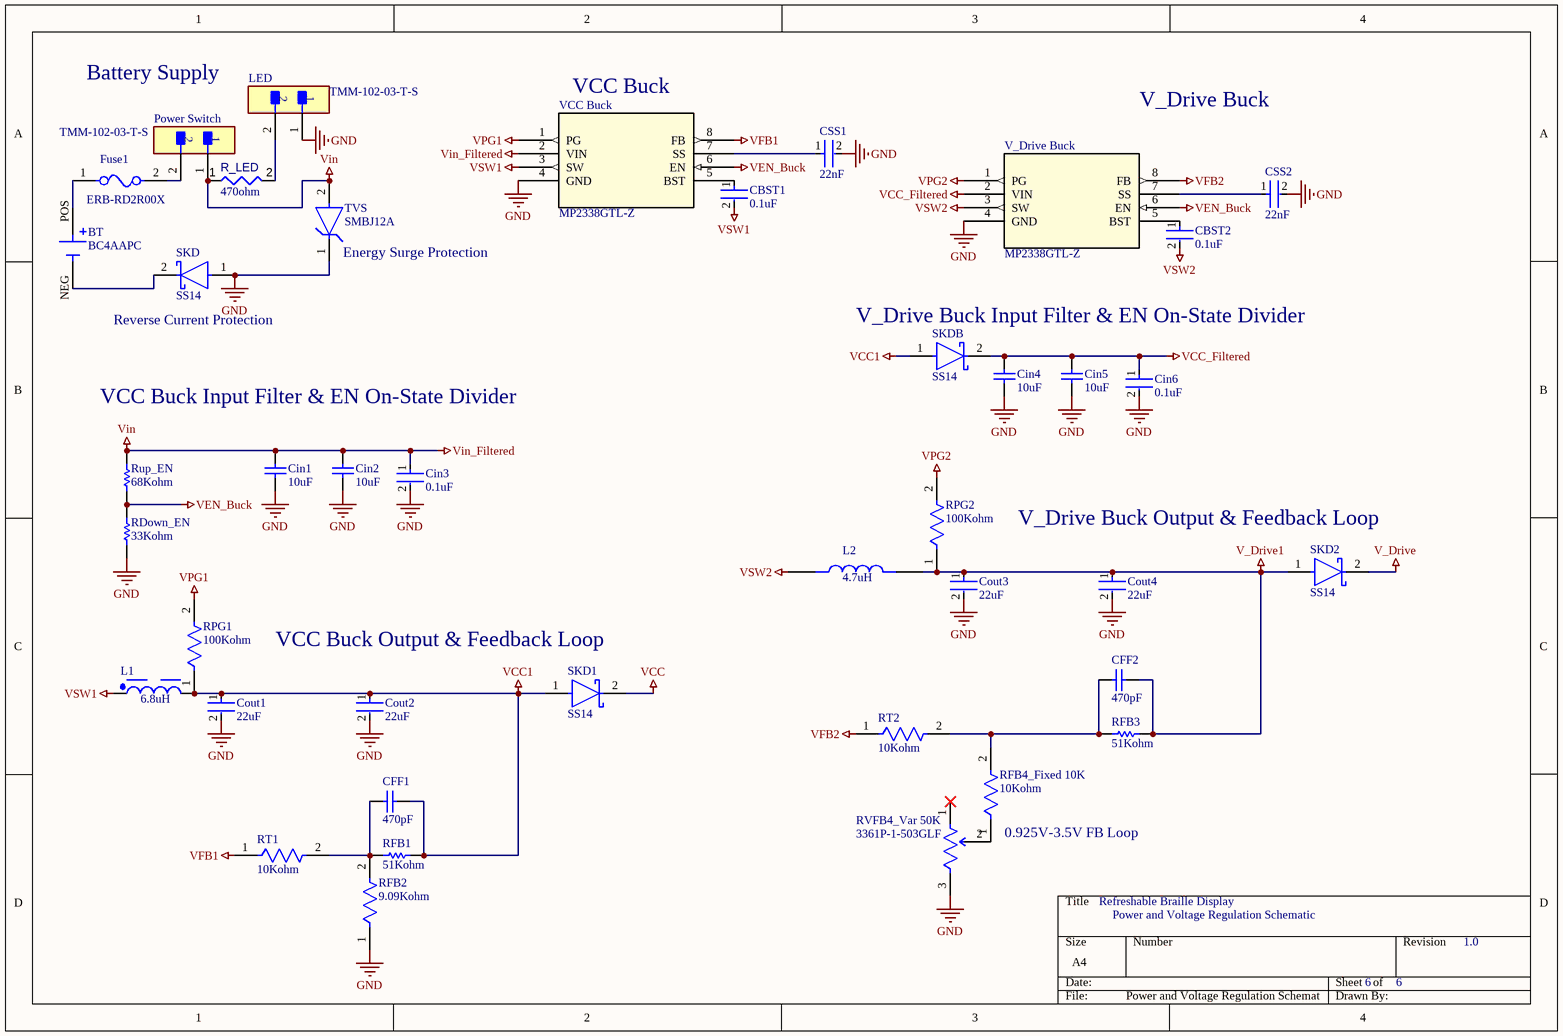
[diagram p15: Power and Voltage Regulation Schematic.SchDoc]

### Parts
BT  BC4AAPC  [BAT_BC4AAPC]
CBST1  0.1uF  [FP-0603B104K500CT-IPC_C]
CBST2  0.1uF  [FP-0603B104K500CT-IPC_C]
CFF1  470pF  [CAPC1608X92X38ML15T08]
CFF2  470pF  [CAPC1608X92X38ML15T08]
Cin1  10uF  [CAPC0603(1608)100_M]
Cin2  10uF  [CAPC0603(1608)100_M]
Cin3  0.1uF  [FP-0603B104K500CT-IPC_C]
Cin4  10uF  [CAPC0603(1608)100_M]
Cin5  10uF  [CAPC0603(1608)100_M]
Cin6  0.1uF  [FP-0603B104K500CT-IPC_C]
Cout1  22uF  [FP-GRM188-0_2-IPC_B]
Cout2  22uF  [FP-GRM188-0_2-IPC_B]
Cout3  22uF  [FP-GRM188-0_2-IPC_B]
Cout4  22uF  [FP-GRM188-0_2-IPC_B]
CSS1  22nF  [FP-CC0603-DA-MFG]
CSS2  22nF  [FP-CC0603-DA-MFG]
Fuse1  ERB-RD2R00X  [FP-ERBRD-MFG]
L1  6.8uH  [WE-LQS_6028]
L2  4.7uH  [IND_ASPI-4030S-4R7M-T]
LED  TMM-102-03-T-S  [FP-TMM-102-03-T-S-MFG]
Power_Switch  TMM-102-03-T-S  [FP-TMM-102-03-T-S-MFG]
R_LED  value 470ohm  [RESC0805(2012)_L]  (hidden comment: 470R5J)
RDown_EN  33Kohm  [RESC2013X70X40LL20T20]
RFB1  51Kohm  [RESC1608X55X25LL10T15]
RFB2  9.09Kohm  [FP-CR0603-IPC_C]
RFB3  51Kohm  [RESC1608X55X25LL10T15]
RFB4_Fixed_10K  10Kohm  [FP-RT0603-MFG]
RPG1  100Kohm  [FP-AC0603-MFG]
RPG2  100Kohm  [FP-AC0603-MFG]
RT1  10Kohm  [FP-RT0603-MFG]
RT2  10Kohm  [FP-RT0603-MFG]
Rup_EN  68Kohm  [RESC2013X70X40LL20T20]
RVFB4_Var_50K  3361P-1-503GLF  [FP-3361P-MFG]
SKD  SS14  [FP-403AE-MFG]
SKD1  SS14  [FP-403AE-MFG]
SKD2  SS14  [FP-403AE-MFG]
SKDB  SS14  [FP-403AE-MFG]
TVS  SMBJ12A  [FP-SMBJ-MFG]
V_Drive_Buck  MP2338GTL-Z  [SOT583_MP2338_MNP]
VCC_Buck  MP2338GTL-Z  [SOT583_MP2338_MNP]

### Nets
GND: Cin1.1 Cin2.1 Cin3.2 Cin4.1 Cin5.1 Cin6.2 Cout1.2 Cout2.2 Cout3.2 Cout4.2 CSS1.2 CSS2.2 LED.1 RDown_EN.1 RFB2.1 RVFB4_Var_50K.3(CW) SKD.1(A) TVS.1(C) V_Drive_Buck.4(GND) VCC_Buck.4(GND)
V_Drive: SKD2.2(C)
V_Drive1: CFF2.2 Cout3.1 Cout4.1 L2.2 RFB3.2 RPG2.1 SKD2.1(A)
VCC: SKD1.2(C)
VCC1: CFF1.2 Cout1.1 Cout2.1 L1.2 RFB1.2 RPG1.1 SKD1.1(A) SKDB.1(A)
VCC_Filtered: Cin4.2 Cin5.2 Cin6.1 SKDB.2(C) V_Drive_Buck.2(VIN)
VEN_Buck: RDown_EN.2 Rup_EN.1 V_Drive_Buck.6(EN) VCC_Buck.6(EN)
VFB1: RT1.1 VCC_Buck.8(FB)
VFB2: RT2.1 V_Drive_Buck.8(FB)
Vin: Cin1.2 Cin2.2 Cin3.1 Power_Switch.1 R_LED.1 Rup_EN.2 TVS.2(A) VCC_Buck.2(VIN)  [also labelled Vin_Filtered]
VPG1: RPG1.2 VCC_Buck.1(PG)
VPG2: RPG2.2 V_Drive_Buck.1(PG)
VSW1: CBST1.2 L1.1 VCC_Buck.3(SW)
VSW2: CBST2.2 L2.1 V_Drive_Buck.3(SW)
NetBT_NEG: BT.NEG SKD.2(C)
NetBT_POS: BT.POS Fuse1.1
NetCBST1_1: CBST1.1 VCC_Buck.5(BST)
NetCBST2_1: CBST2.1 V_Drive_Buck.5(BST)
NetCFF1_1: CFF1.1 RFB1.1 RFB2.2 RT1.2
NetCFF2_1: CFF2.1 RFB3.1 RFB4_Fixed_10K.2 RT2.2
NetCSS1_1: CSS1.1 VCC_Buck.7(SS)
NetCSS2_1: CSS2.1 V_Drive_Buck.7(SS)
NetFuse1_2: Fuse1.2 Power_Switch.2
NetLED_2: LED.2 R_LED.2
NetRFB4_Fixed_10K_1: RFB4_Fixed_10K.1 RVFB4_Var_50K.2(WIPER)

Not connected (* = marked no-connect by the designer): RVFB4_Var_50K 1(CCW)*

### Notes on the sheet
- Battery Supply
- (near VCC_Buck) VCC Buck
- V_Drive Buck
- (near TVS) Energy Surge Protection
- (near SKD) Reverse Current Protection
- V_Drive Buck Input Filter & EN On-State Divider
- VCC Buck Input Filter & EN On-State Divider
- V_Drive Buck Output & Feedback Loop
- VCC Buck Output & Feedback Loop
- (near RFB4_Fixed_10K) 0.925V-3.5V FB Loop
- Refreshable Braille Display
- Power and Voltage Regulation Schematic
- 6
- 1.0

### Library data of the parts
BT = BC4AAPC: BATTERY HOLDER AA 4 CELL PC PIN; MF: MPD
CBST1 CBST2 Cin3 Cin6 = CMP-45632-000007-1: CAP CER 0.1UF 50V X7R 0603; Tolerance: 10%; Capacitance: 100nF
CFF1 CFF2 = CMP-1035-01681-2: VJ0603Y471KXBAC; Manufacturer: Vitramon
Cin1 Cin2 Cin4 Cin5 = CMP-1035-02796-1: CAP 10uF 6.3V ±10% 0603 (1608 Metric) Thickness 1mm SMD; Case-EIA: 0603; Tolerance: Â±10%; Case-Metric: 1608
Cout1-Cout4 = CMP-06035-001854-1: Chip Multilayer Ceramic Capacitors for General Purpose, 0603, 22uF, X6S, 22%, 20%, 6.3V GRM188C80J226ME15D
CSS1 CSS2 = CMP-03422-000397-1: CC0603 22 nF X7R 20.00% 50 V; Manufacturer Part Number: CC0603MRX7R9BB223; Manufacturer: YAGEO; Tolerance: 0.2; Temperature Coefficient: 15%; Voltage: 50 V
Fuse1 = CMP-05590-000001-1: FUSE BOARD MOUNT 2A 32VDC 0402; Manufacturer: Panasonic Electronic Components; Resistance: 53mΩ; Value: 53mΩ; Voltage Rating: 32V; Fuse Interrupt Dc Current: 35A; Fuse Blow Speed: Fast
L1 = CMP-1354-00061-2: 74404063068; NexarPartId: 46948278; Saturation Current: 2.8A; Inductance Tolerance: 20%; Test Frequency: 100kHz; Core Material: Ferrite; DC Resistance (DCR): 47mΩ; RMS Current (Irms): 2.4A; Series Resistance: 61.1mΩ; Shielding: Shielded; Inductance: 6.8µH; Self Resonant Frequency: 40MHz
L2 = ASPI-4030S-4R7M-T: 4.7 ÂµH Shielded Drum Core, Wirewound Inductor 2 A 60mOhm Nonstandard ASPI-4030S-4R7M-T; MF: Abracon LLC
LED Power_Switch = CMP-02766-001621-1: as Back_Button on sheet MCU Schematic
R_LED = CMP-009-00102-2: 470R 0.125W 5% 0805 (2012 Metric)  SMD; Power: 125mW
RDown_EN = CMP-2001-00401-1: ERJ-6GEYJ333V; Manufacturer: Panasonic
RFB1 RFB3 = CMP-2000-04226-1: RC0603FR-1351KL; Manufacturer: Yageo
RFB2 = CMP-07231-003312-1: Thick Film Chip Resistors 0603 9.09kΩ 0.1W 1% 100ppm/°C  CR0603-FX-9091ELF; Max Power Dissipation: 100mW; Voltage Rating: 50V; Resistance: 9.09kR
RFB4_Fixed_10K RT1 RT2 = CMP-03412-024264-1: RT0603 10KΩ 0.1W 50 ppm/°C 1.00% RT0603FRE1010KL; Manufacturer: Yageo; Voltage Rating: 75V; Tolerance: 0.01
RPG1 RPG2 = CMP-03412-022575-2: RES 100KΩ 1.00% 0.1W 0603 AC0603FR-10100KL; Tolerance: 1%; Resistance: 100kR
Rup_EN = CMP-2001-00442-1: ERJ-6GEYJ683V; Manufacturer: Panasonic
RVFB4_Var_50K = CMP-07234-000057-1: TRIMMER 50K OHM 0.5W GW TOP ADJ; Power Rating: 500mW; Voltage Rating: 300V; Resistance Tolerance: 10%; Number of Turns: 1; Resistance: 50kR; Temperature Coefficient: 100ppm/°C
SKD SKD1 SKD2 SKDB = CMP-2000-04943-2: DIODE SCHOTTKY 40V 1A SMA; Manufacturer: ON Semiconductor; Peak Reverse Current: 0.2mA; Max Junction Temp: +125°C; Standoff Height: 0.05mm; Max Surge Forward Current: 40A
TVS = CMP-2000-07093-2: TVS DIODE 12V 19.9V DO214AA; Manufacturer: Littelfuse; Breakdown Voltage: 13.3V; Peak Pulse Current: 30.2A; Max Junction Temp: +150°C; Peak Pulse Power: 600W; Direction: Unidirectional; Number Of Channels: 1
V_Drive_Buck VCC_Buck = MP2338GTL-Z: High-Efficiency 28V 3A 450kHz Synchronous Step-Down Converter In SOT583 Package; Manufacturer_Name: Monolithic Power Systems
